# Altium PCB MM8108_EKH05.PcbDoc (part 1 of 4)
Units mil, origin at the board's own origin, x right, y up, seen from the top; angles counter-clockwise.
Board outline 6023.62 x 3425.2 mil, 4 copper layers (Top Layer, Ground Plane, Middle Layer, Bottom Layer), stack 76.15 mil thick; 188 components, 156 nets, 687 pads, 1369 vias.
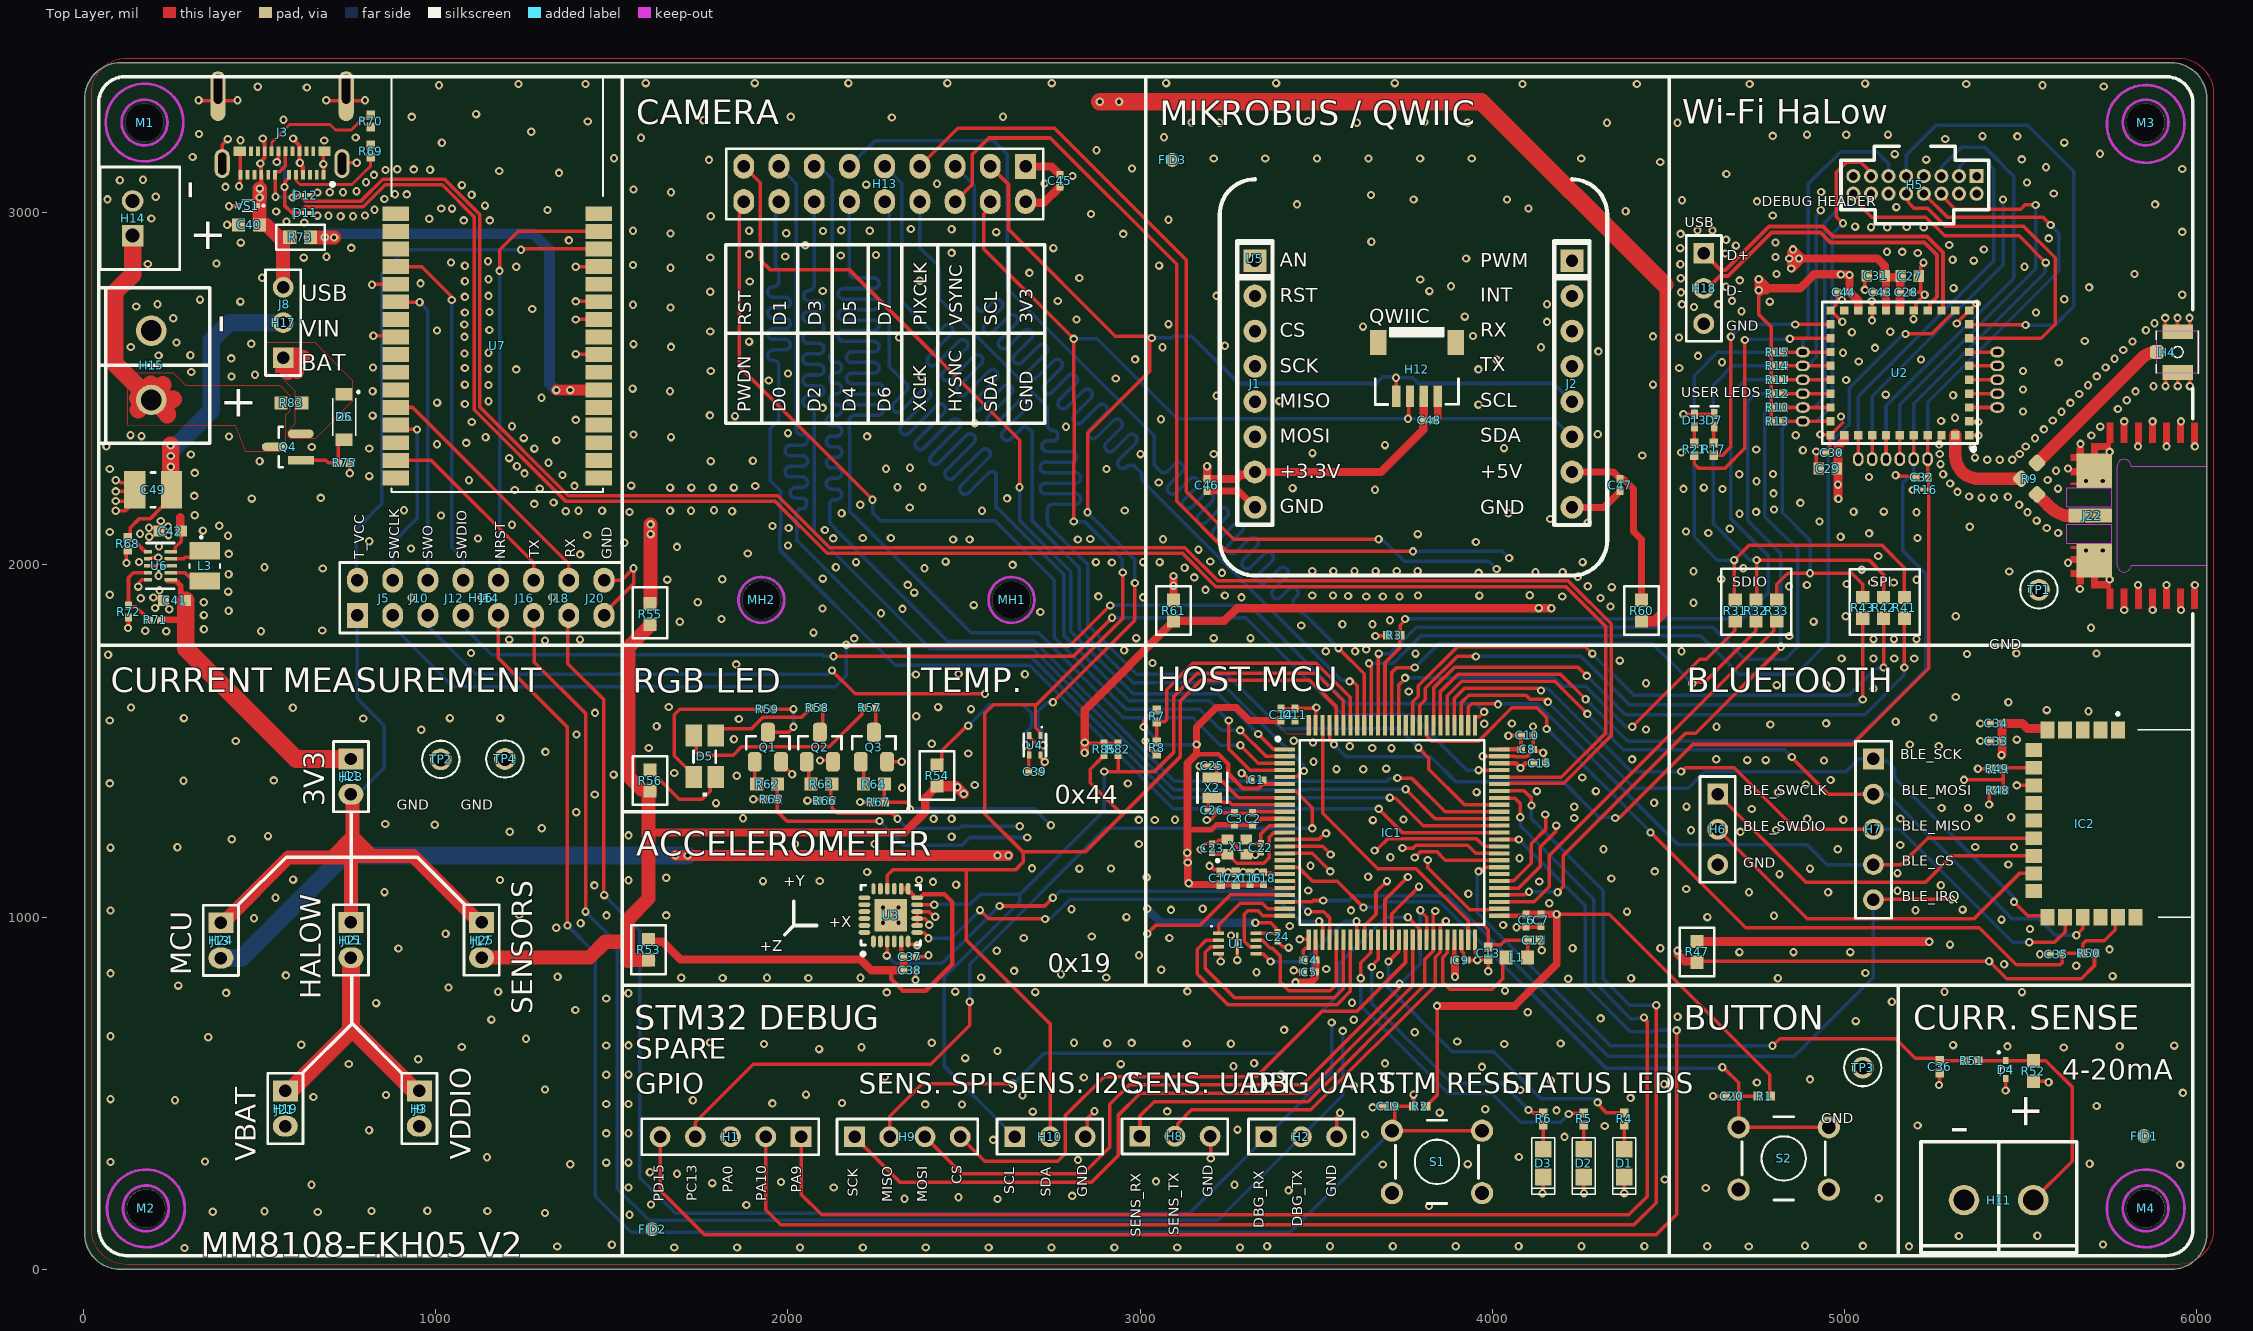
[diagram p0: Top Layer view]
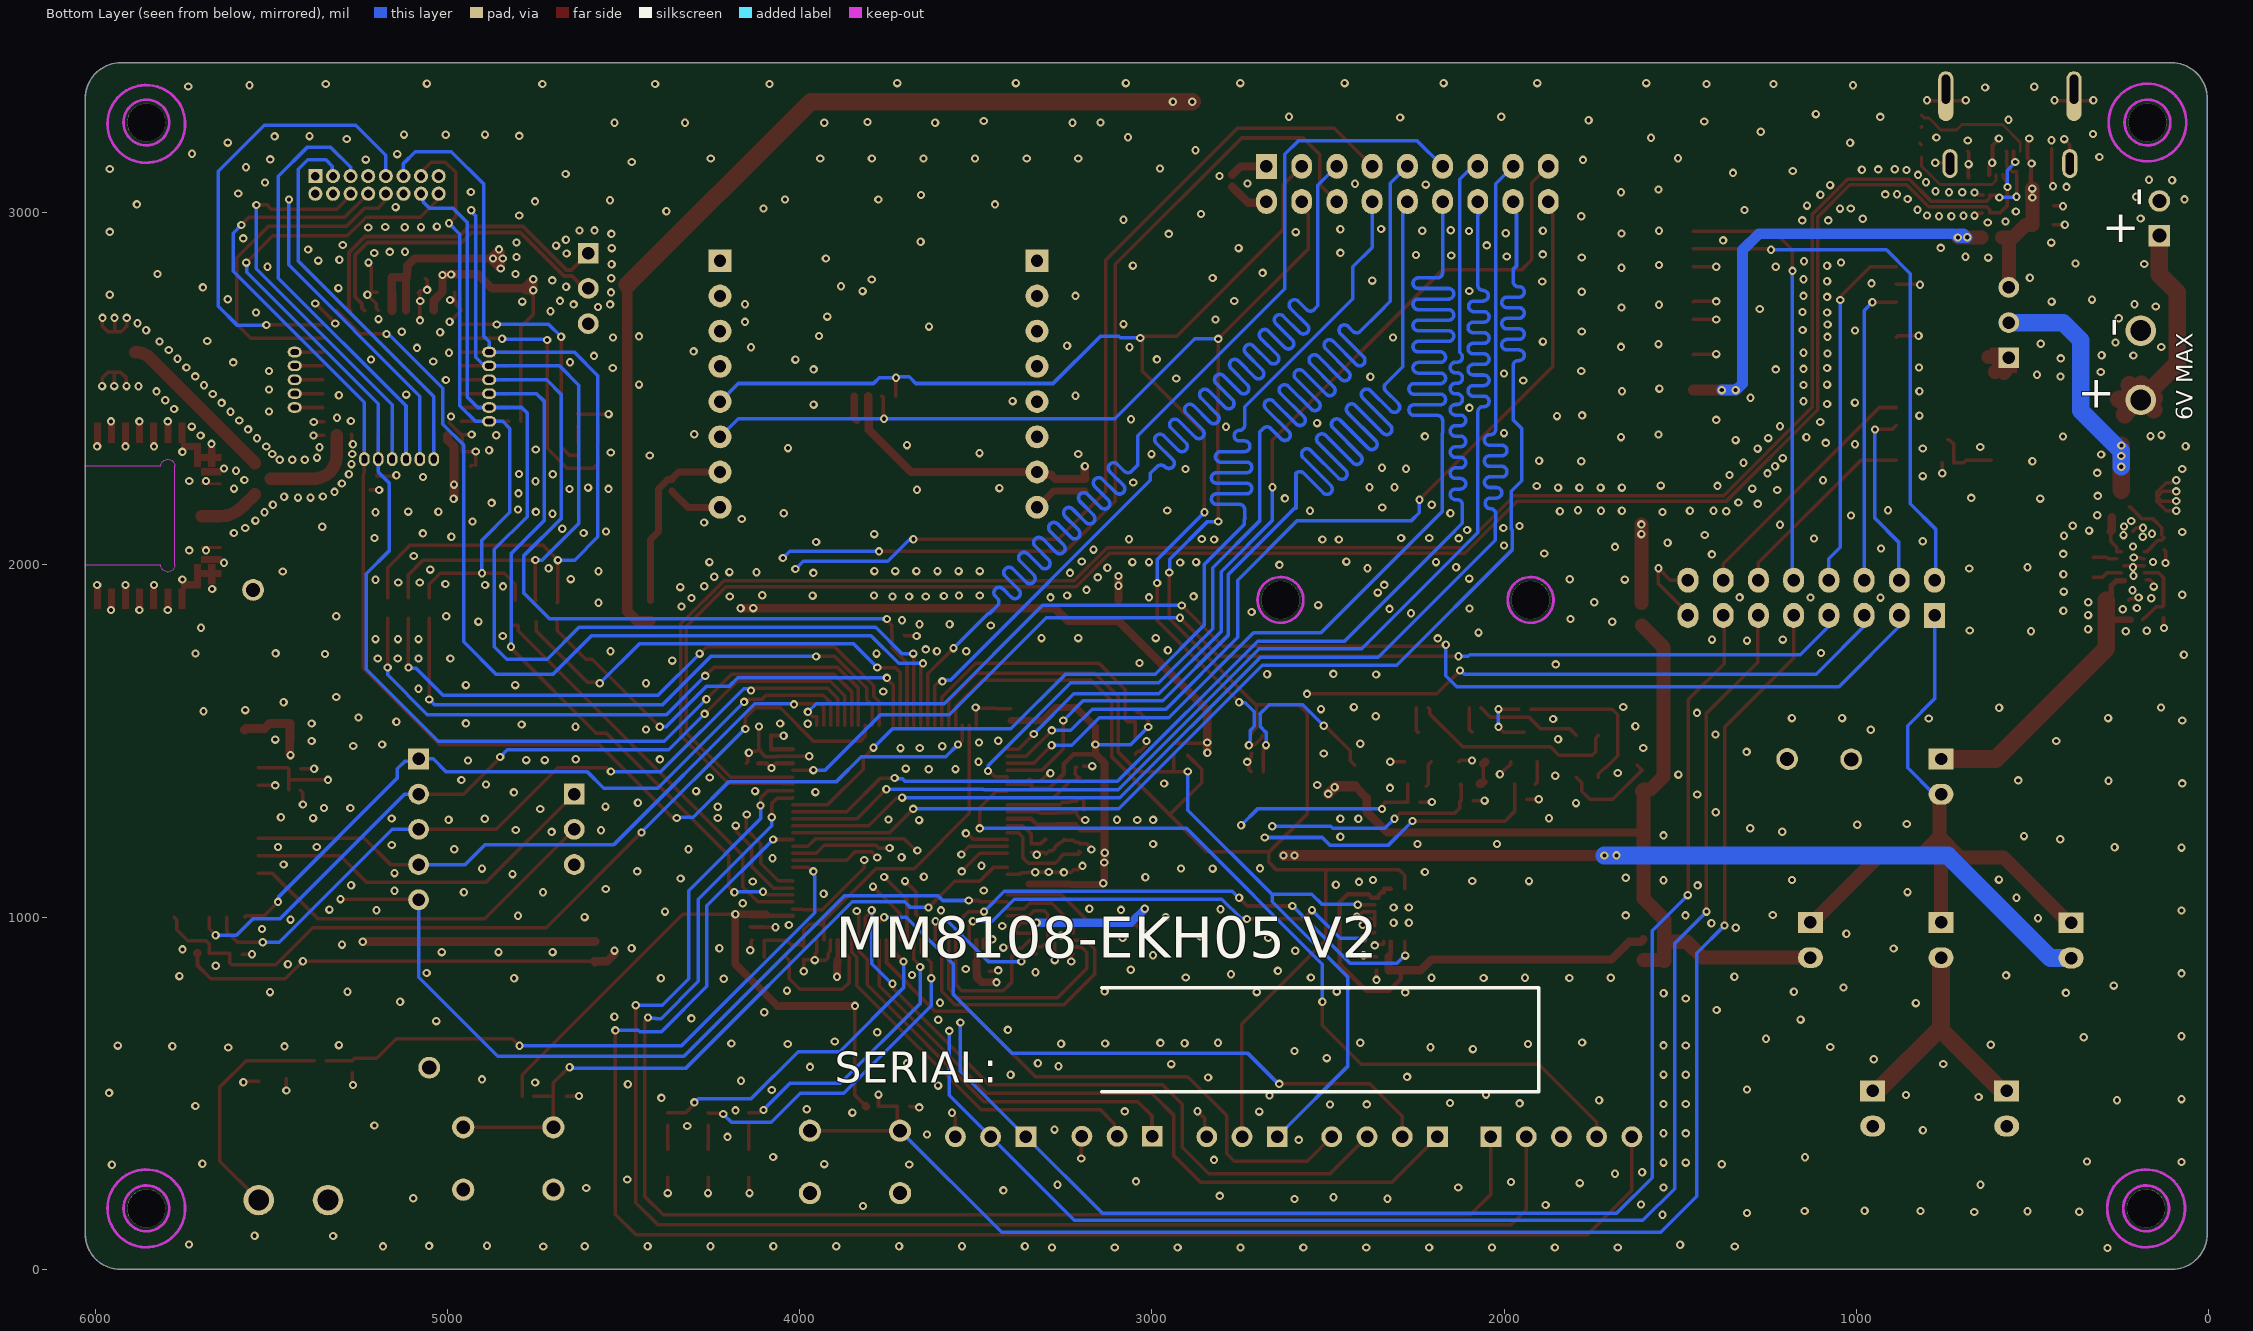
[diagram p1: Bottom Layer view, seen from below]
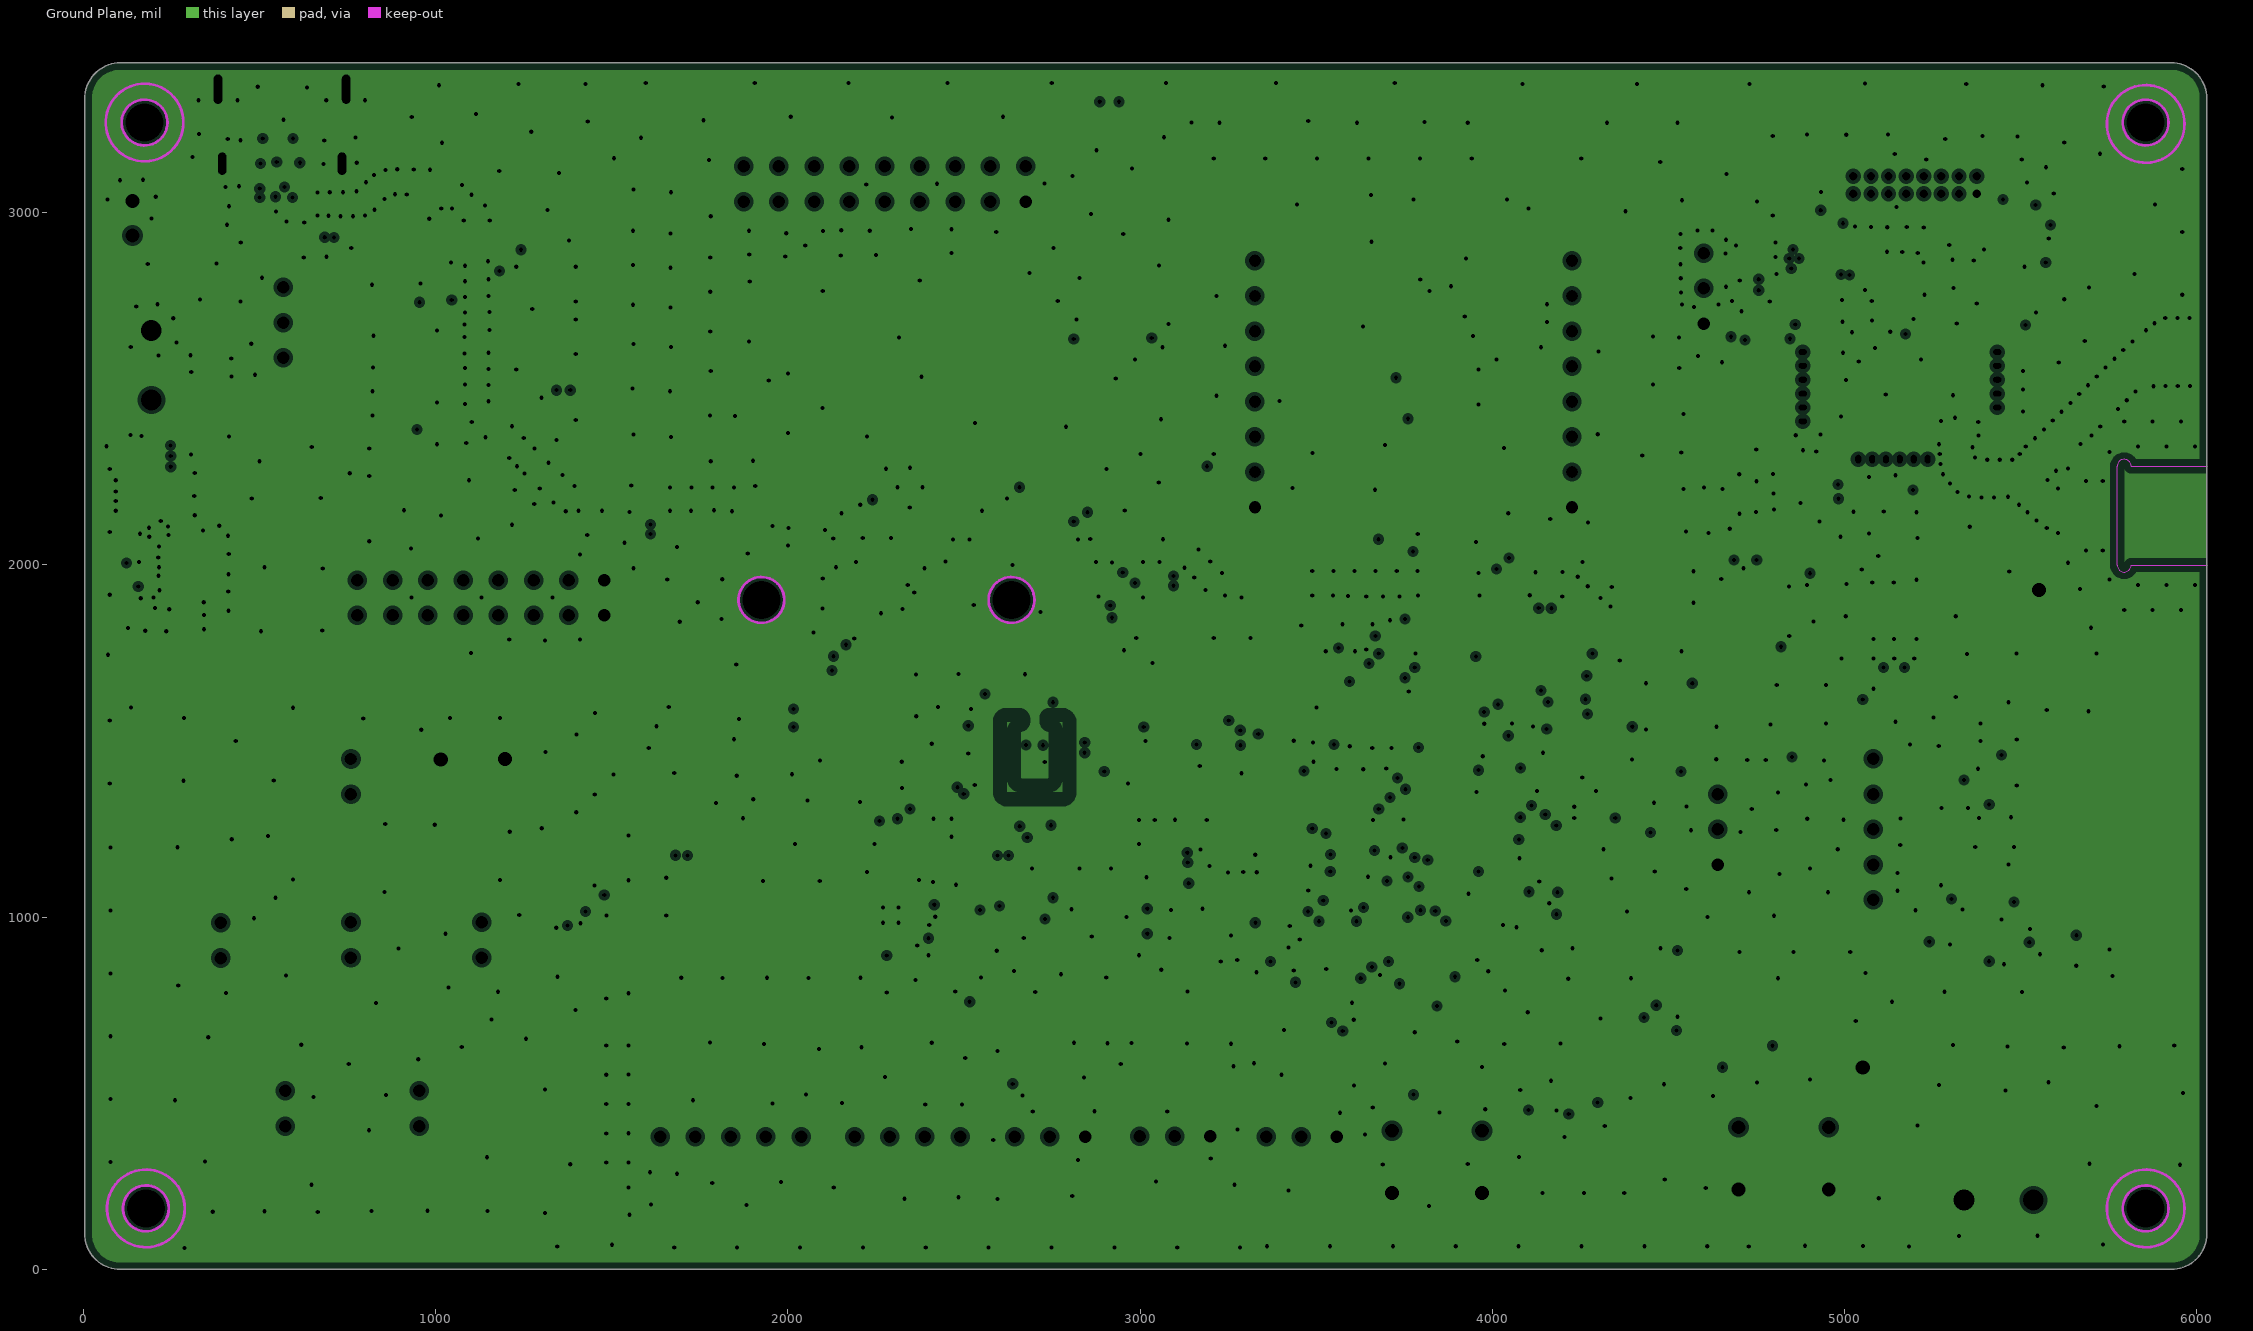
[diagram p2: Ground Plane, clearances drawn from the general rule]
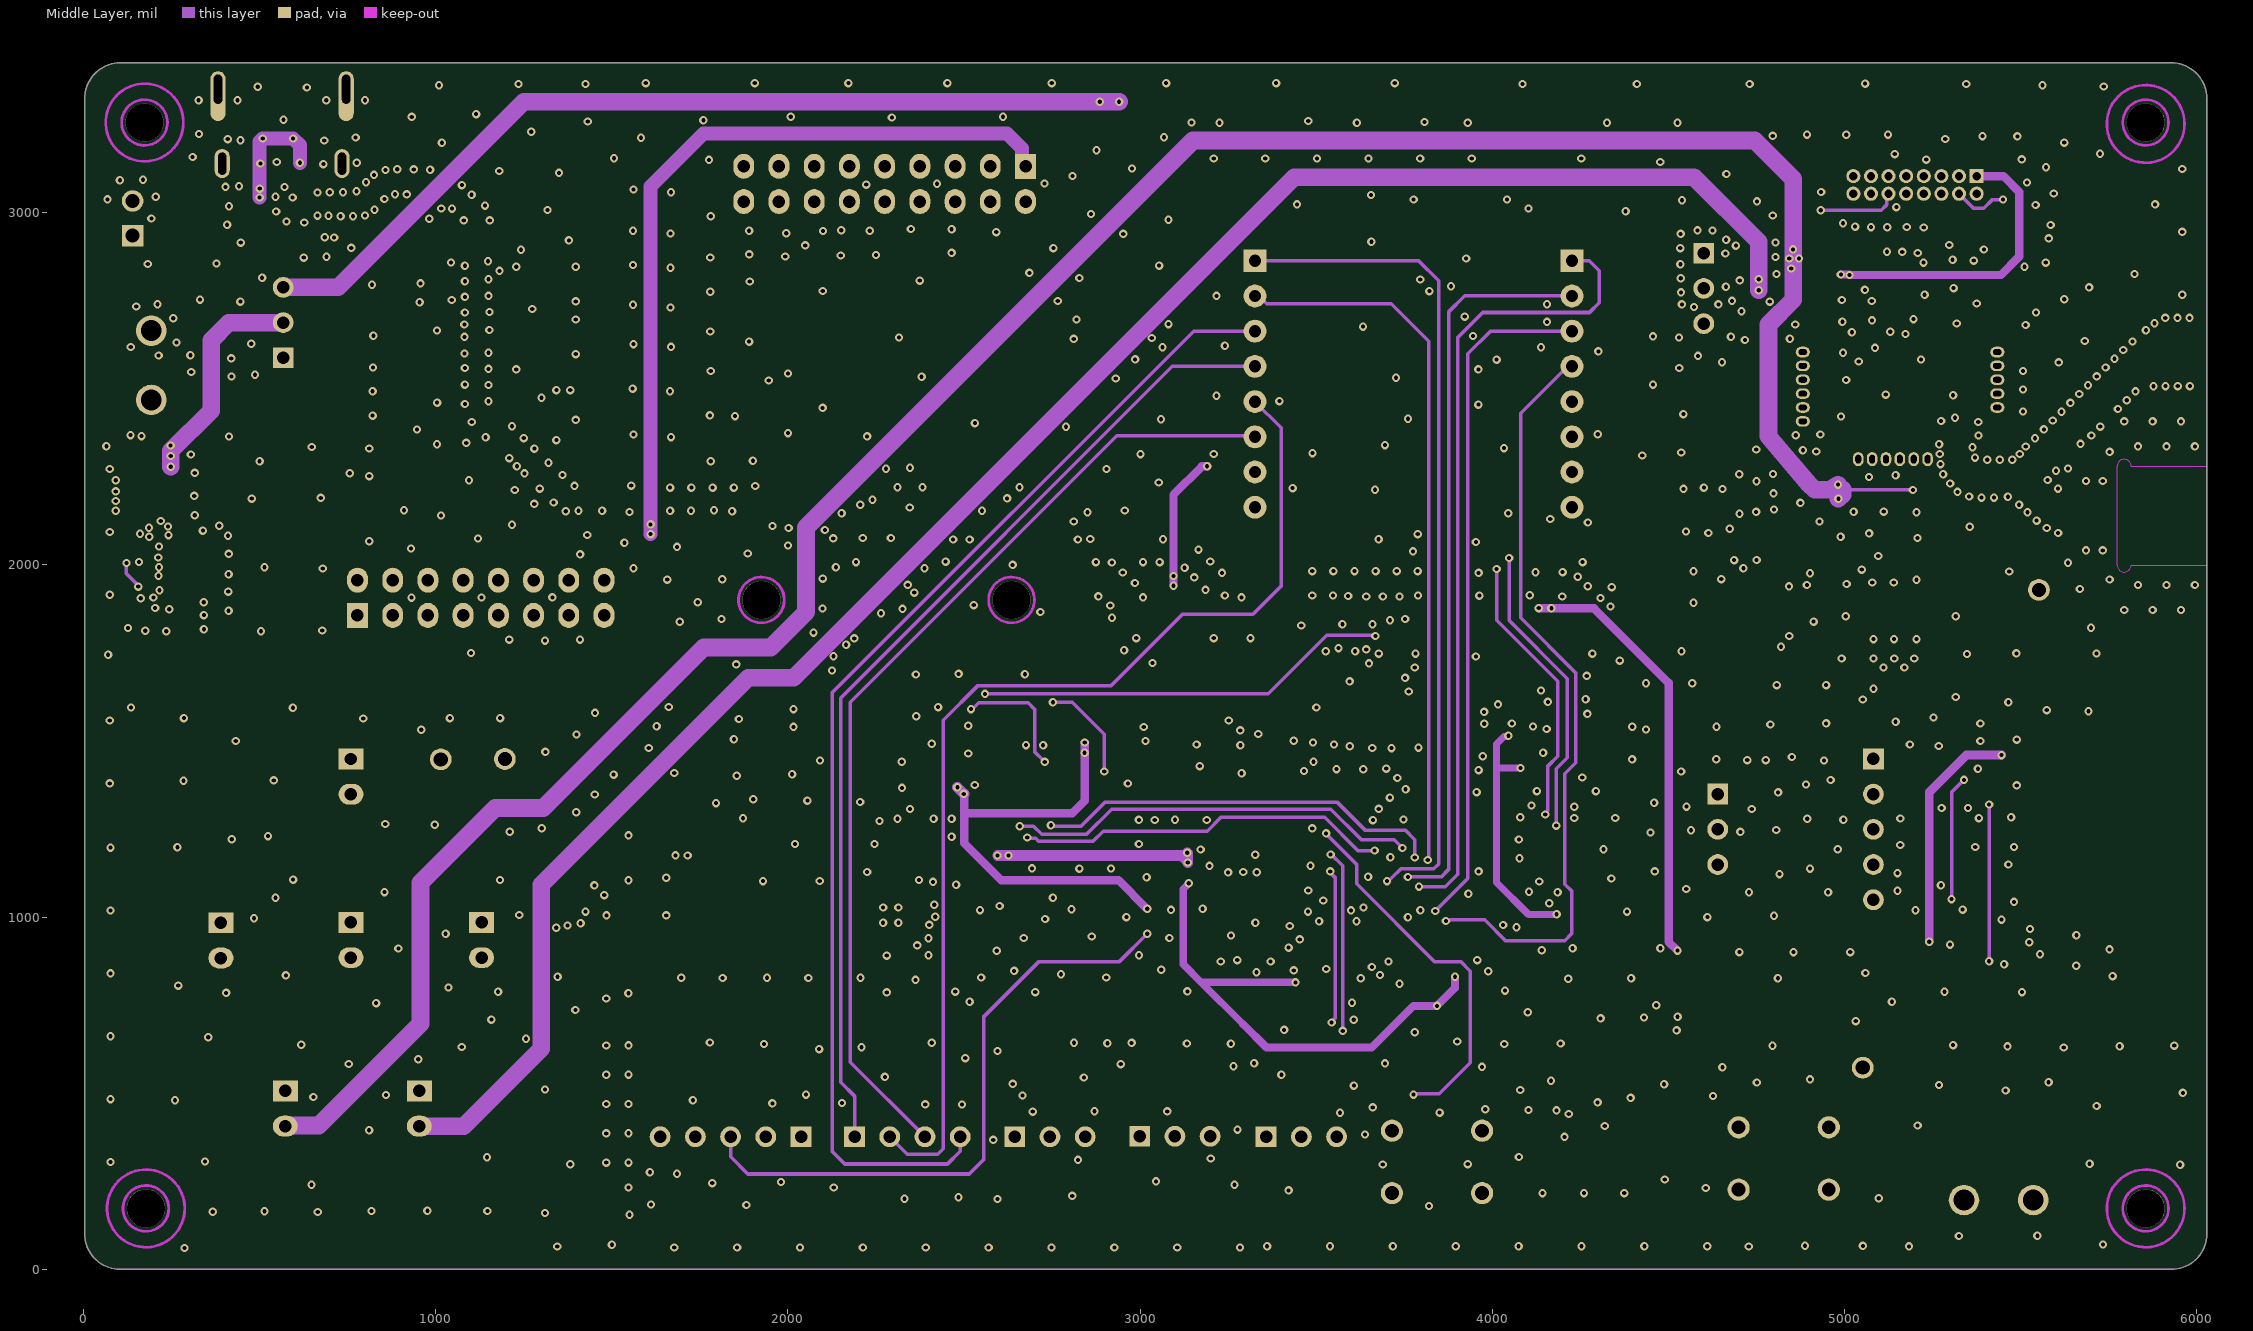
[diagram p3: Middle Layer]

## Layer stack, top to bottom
Top Solder: solder mask 0.8, SM-001, Dk 3.8
Top Layer: signal copper 1.4
Dielectric 2: prepreg 13.2, PP-006, Dk 4.11
Ground Plane: plane copper 1.25, net GND
Dielectric 1: prepreg 44.5, Core, Dk 4
Middle Layer: signal copper 1.25
Dielectric 5: prepreg 13.15, PP-006, Dk 4.11
Bottom Layer: signal copper 1.4
Bottom Solder: solder mask 0.8, SM-001, Dk 3.8

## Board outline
3.94,3188.98 3.94,3325.2 cw(c103.94,3325.2) 103.94,3425.2 5927.56,3425.2 cw(c5927.56,3325.2) 6027.56,3325.2 6027.56,100 cw(c5927.56,100) 5927.56,0 103.94,0 cw(c103.94,100) 3.94,100 3.94,275.59

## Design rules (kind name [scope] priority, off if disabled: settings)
AssemblyTestPointUsage [All] p0: scope1count=1 scope1_0_kind=Board scope1_0_value=Board scope2count=1 scope2_0_kind=Board scope2_0_value=Board commentlength=0
AssemblyTestPointUsage [All] p1: allowmultiple=TRUE
AssemblyTestpoint [All] p0: scope1count=1 scope1_0_kind=Board scope1_0_value=Board scope2count=1 scope2_0_kind=Board scope2_0_value=Board commentlength=0
AssemblyTestpoint [All] p1: testpointundercomponent=TRUE minsize=40 maxsize=100 preferedsize=60 minholesize=0 maxholesize=40 preferedholesize=32 testpointgrid=1 usegrid=FALSE gridtolerance=0.01 allowsidetop=TRUE
BoardOutlineClearance [All] p0 off: scope1count=1 scope1_0_kind=Board scope1_0_value=Board scope2count=1 scope2_0_kind=Board scope2_0_value=Board commentlength=140 gap=12 // Protel DXP Scope 1 Expression Was: (not OnTopSilkscreen) AND (NOT OnBottomSilkscreen) and (not OnMultiLayer) and (not InComponent('H3'))
BoardOutlineClearance [(not OnTopSilkscreen) AND (NOT OnBottomSilkscreen) and (not OnMultiLayer) and (not InComponent('H3'))] p1: gap=12 ignorepadtopadclearanceinfootprint=FALSE
Clearance Clearance_RF [All] p0: scope1count=1 scope1_0_kind=NetClass scope1_0_value="50 OHMs" scope2count=1 scope2_0_kind=Board scope2_0_value=Board commentlength=0 gap=78.74
Clearance Clearance_SMA [All] p0: scope1count=1 scope1_0_kind=Component scope1_0_value=J22 scope2count=1 scope2_0_kind=Component scope2_0_value=J22 commentlength=0 gap=0.01
Clearance Clearance_1 [All] p0: scope1count=1 scope1_0_kind=Board scope1_0_value=Board scope2count=1 scope2_0_kind=Board scope2_0_value=Board commentlength=0 gap=6
Clearance Clearance_USB [All] p0 off: scope1count=1 scope1_0_kind=Board scope1_0_value=Board scope2count=1 scope2_0_kind=Board scope2_0_value=Board commentlength=65 gap=6 // Protel DXP Scope 1 Expression Was: InDifferentialPair('USBC')
Clearance Clearance_RF_Poly [All] p0 off: scope1count=1 scope1_0_kind=Board scope1_0_value=Board scope2count=1 scope2_0_kind=NetClass scope2_0_value="50 OHMs" commentlength=50 gap=6.61 // Protel DXP Scope 1 Expression Was: (InPolygon)
Clearance Clearance_RF_Poly [(InPolygon) vs InNetClass('50 OHMs')] p1: gap=6.61 ignorepadtopadclearanceinfootprint=TRUE
Clearance Clearance_SMA [InComponent('J22') vs InComponent('J22')] p2: gap=0.01 ignorepadtopadclearanceinfootprint=TRUE
Clearance Clearance_USB [InDifferentialPair('USBC')] p3: gap=6 ignorepadtopadclearanceinfootprint=TRUE
Clearance Clearance_1 [All] p4: gap=6 ignorepadtopadclearanceinfootprint=TRUE
Clearance Clearance_RF [InNetClass('50 OHMs')] p5: gap=78.74 ignorepadtopadclearanceinfootprint=TRUE except(1.97: Arc-Arc Arc-Track Arc-SMDPad Arc-THPad Track-Track Track-SMDPad Track-THPad)
ComponentClearance [All] p0: scope1count=1 scope1_0_kind=Board scope1_0_value=Board scope2count=1 scope2_0_kind=Board scope2_0_value=Board commentlength=0 gap=10 collisioncheckmode=3
DiffPairsRouting DiffPairsRouting_MM [All] p0 off: scope1count=1 scope1_0_kind=Board scope1_0_value=Board scope2count=1 scope2_0_kind=Board scope2_0_value=Board commentlength=66 // Protel DXP Scope 1 Expression Was: InDifferentialPair('USB_D')
DiffPairsRouting DiffPairsRouting_USBC [All] p0 off: scope1count=1 scope1_0_kind=Board scope1_0_value=Board scope2count=1 scope2_0_kind=Board scope2_0_value=Board commentlength=65 // Protel DXP Scope 1 Expression Was: InDifferentialPair('USBC')
DiffPairsRouting DiffPairsRouting_MM [InDifferentialPair('USB_D')] p1: maxlimit=10 minlimit=6 mostfreqgap=10 toplayer_maxgap=6 toplayer_prefgap=6 toplayer_minwidth=11.13 toplayer_maxwidth=11.13 toplayer_prefwidth=11.13 impedanceprofiledriven=TRUE impedanceprofileid={FA8D62EB-FDD2-4305-96CF-BF7F0CD6B75F} impedanceprofilevalue=90.000000 maxuncoupledlength=500
DiffPairsRouting DiffPairsRouting_USBC [InDifferentialPair('USBC')] p2 off: maxlimit=10 minlimit=5 mostfreqgap=10 toplayer_mingap=6 toplayer_maxgap=6 toplayer_prefgap=6 toplayer_minwidth=11.13 toplayer_maxwidth=11.13 toplayer_prefwidth=11.13 impedanceprofiledriven=TRUE impedanceprofileid={FA8D62EB-FDD2-4305-96CF-BF7F0CD6B75F} impedanceprofilevalue=90.000000 maxuncoupledlength=500
FabricationTestPointUsage [All] p0 off: scope1count=1 scope1_0_kind=Board scope1_0_value=Board scope2count=1 scope2_0_kind=Board scope2_0_value=Board commentlength=0 valid=0 allowmultiple=FALSE
FabricationTestPointUsage [All] p1 off: valid=0 allowmultiple=FALSE
FabricationTestpoint [All] p0 off: scope1count=1 scope1_0_kind=Board scope1_0_value=Board scope2count=1 scope2_0_kind=Board scope2_0_value=Board commentlength=63 side=1 testpointundercomponent=TRUE minsize=40 maxsize=100 preferedsize=60 minholesize=0 maxholesize=40 preferedholesize=32 testpointgrid=1 // Protel DXP Scope 1 Expression Was: (IsPad And OnMultiLayer)
FabricationTestpoint [(IsPad And OnMultiLayer)] p1 off: side=1 testpointundercomponent=TRUE minsize=40 maxsize=100 preferedsize=60 minholesize=0 maxholesize=40 preferedholesize=32 testpointgrid=1 allowsidetop=TRUE usegrid=TRUE gridtolerance=0.01
FanoutControl Fanout_Default [All] p0 off: scope1count=1 scope1_0_kind=Board scope1_0_value=Board scope2count=1 scope2_0_kind=Board scope2_0_value=Board commentlength=30 // Fanout_Default (Default Rule)
FanoutControl Fanout_Small [All] p0 off: scope1count=1 scope1_0_kind=Board scope1_0_value=Board scope2count=1 scope2_0_kind=Board scope2_0_value=Board commentlength=84 // Protel DXP Scope 1 Expression Was: (CompPinCount < 5)   Fanout_Small (Default Rule)
FanoutControl Fanout_SOIC [All] p0 off: scope1count=1 scope1_0_kind=Board scope1_0_value=Board scope2count=1 scope2_0_kind=Board scope2_0_value=Board commentlength=71 // Protel DXP Scope 1 Expression Was: IsSOIC   Fanout_SOIC (Default Rule)
FanoutControl Fanout_LCC [All] p0 off: scope1count=1 scope1_0_kind=Board scope1_0_value=Board scope2count=1 scope2_0_kind=Board scope2_0_value=Board commentlength=69 // Protel DXP Scope 1 Expression Was: IsLCC   Fanout_LCC (Default Rule)
FanoutControl Fanout_BGA [All] p0 off: scope1count=1 scope1_0_kind=Board scope1_0_value=Board scope2count=1 scope2_0_kind=Board scope2_0_value=Board commentlength=69 // Protel DXP Scope 1 Expression Was: IsBGA   Fanout_BGA (Default Rule)
FanoutControl Fanout_BGA [IsBGA] p1 off: bgadir=Out bgaviamode=Centered fanoutstyle=Auto fanoutdirection=Alternating viagrid=1 // Fanout_BGA (Default Rule)
FanoutControl Fanout_LCC [IsLCC] p2 off: bgadir=Out bgaviamode=Centered fanoutstyle=Auto fanoutdirection=Alternating viagrid=1 // Fanout_LCC (Default Rule)
FanoutControl Fanout_SOIC [IsSOIC] p3 off: bgadir=Out bgaviamode=Centered fanoutstyle=Auto fanoutdirection=Alternating viagrid=1 // Fanout_SOIC (Default Rule)
FanoutControl Fanout_Small [(CompPinCount < 5)] p4 off: bgadir=Out bgaviamode=Centered fanoutstyle=Auto fanoutdirection=OutThenIn viagrid=1 // Fanout_Small (Default Rule)
FanoutControl Fanout_Default [All] p5 off: bgadir=Out bgaviamode=Centered fanoutstyle=Auto fanoutdirection=Alternating viagrid=1 // Fanout_Default (Default Rule)
Height [All] p0 off: scope1count=1 scope1_0_kind=Board scope1_0_value=Board scope2count=1 scope2_0_kind=Board scope2_0_value=Board commentlength=0
Height "Under Socket" [All] p0 off: scope1count=1 scope1_0_kind=Board scope1_0_value=Board scope2count=1 scope2_0_kind=Board scope2_0_value=Board commentlength=64 // Protel DXP Scope 1 Expression Was: WithinRoom('ROOM_SOCKET')
Height "POGO Pins" [All] p0: scope1count=1 scope1_0_kind=ComponentClass scope1_0_value=POGO scope2count=1 scope2_0_kind=Board scope2_0_value=Board commentlength=0
Height TP1 [All] p0: scope1count=1 scope1_0_kind=Component scope1_0_value=TP1 scope2count=1 scope2_0_kind=Board scope2_0_value=Board commentlength=0
Height TP1 [InComponent('TP1')] p1: minheight=0 maxheight=472.44 prefheight=118.11
Height "POGO Pins" [InComponentClass('POGO')] p2: minheight=0 maxheight=275.59 prefheight=196.85
Height "Under Socket" [WithinRoom('ROOM_SOCKET')] p3: minheight=0 maxheight=157.48 prefheight=118.11
Height [All] p4 off: minheight=0 maxheight=1000 prefheight=500
HoleSize [All] p0: scope1count=1 scope1_0_kind=Board scope1_0_value=Board scope2count=1 scope2_0_kind=Board scope2_0_value=Board commentlength=0 absolutevalues=TRUE maxlimit=200 minlimit=6 maxpercent=80.000 minpercent=20.000
HoleSize [All] p1: absolutevalues=TRUE maxlimit=200 minlimit=6 maxpercent=80.000 minpercent=20.000
HoleToHoleClearance [All] p0: scope1count=1 scope1_0_kind=Board scope1_0_value=Board scope2count=1 scope2_0_kind=Board scope2_0_value=Board commentlength=0
HoleToHoleClearance [All] p1: gap=8 allowstackedmicrovias=TRUE
LayerPairs [All] p0 off: scope1count=1 scope1_0_kind=Board scope1_0_value=Board scope2count=1 scope2_0_kind=Board scope2_0_value=Board commentlength=0 enforce=TRUE
LayerPairs [All] p1 off: enforce=TRUE
MatchedLengths SDIO_2 [All] p0: scope1count=1 scope1_0_kind=NetClass scope1_0_value=SDIO_2 scope2count=1 scope2_0_kind=Board scope2_0_value=Board commentlength=0 tolerance=2000 amplitude=200 gap=20 style=90-Degree
MatchedLengths DCMI [All] p0: scope1count=1 scope1_0_kind=NetClass scope1_0_value=DCMI scope2count=1 scope2_0_kind=Board scope2_0_value=Board commentlength=0 tolerance=1000 amplitude=200 gap=20 style=90-Degree
MatchedLengths SDIO [All] p0: scope1count=1 scope1_0_kind=NetClass scope1_0_value=SDIO scope2count=1 scope2_0_kind=Board scope2_0_value=Board commentlength=0 tolerance=2000 amplitude=200 gap=20 style=90-Degree
MatchedLengths MatchLengths_U1_Passives_J5 [All] p0 off: scope1count=1 scope1_0_kind=Board scope1_0_value=Board scope2count=1 scope2_0_kind=Board scope2_0_value=Board commentlength=98 tolerance=50 amplitude=200 gap=20 style=90-Degree // Protel DXP Scope 1 Expression Was: InxSignalClass('xSignals_U1_Passives_J5_MatchLengthsClass')
MatchedLengths MatchLengths_U1_Passives_J5_1 [All] p0 off: scope1count=1 scope1_0_kind=Board scope1_0_value=Board scope2count=1 scope2_0_kind=Board scope2_0_value=Board commentlength=100 tolerance=50 amplitude=200 gap=20 style=90-Degree // Protel DXP Scope 1 Expression Was: InxSignalClass('xSignals_U1_Passives_J5_MatchLengthsClass_1')
MatchedLengths DCMI [InNetClass('DCMI')] p1: tolerance=1000 checknetsindiffpair=FALSE checkdiffpairvsdiffpair=TRUE checkxsignals=TRUE checkothers=TRUE
MatchedLengths SDIO [InNetClass('SDIO')] p2: tolerance=2000 checknetsindiffpair=FALSE checkdiffpairvsdiffpair=TRUE checkxsignals=TRUE checkothers=TRUE
MatchedLengths SDIO_2 [InNetClass('SDIO_2')] p3: tolerance=2000 checknetsindiffpair=FALSE checkdiffpairvsdiffpair=TRUE checkxsignals=TRUE checkothers=TRUE
MatchedLengths MatchLengths_U1_Passives_J5_1 [InxSignalClass('xSignals_U1_Passives_J5_MatchLengthsClass_1')] p4: tolerance=50 checknetsindiffpair=FALSE checkdiffpairvsdiffpair=TRUE checkxsignals=TRUE checkothers=TRUE
MatchedLengths MatchLengths_U1_Passives_J5 [InxSignalClass('xSignals_U1_Passives_J5_MatchLengthsClass')] p5: tolerance=50 checknetsindiffpair=FALSE checkdiffpairvsdiffpair=TRUE checkxsignals=TRUE checkothers=TRUE
MinimumSolderMaskSliver [All] p0 off: scope1count=1 scope1_0_kind=Board scope1_0_value=Board scope2count=1 scope2_0_kind=Board scope2_0_value=Board commentlength=96 // Protel DXP Scope 1 Expression Was: not InComponent('U4','U1','U5','U6','U7','U8','U9','U10')
MinimumSolderMaskSliver [not InComponent('U4','U1','U5','U6','U7','U8','U9','U10')] p1: minsoldermaskwidth=1
NetAntennae [All] p0: scope1count=1 scope1_0_kind=Board scope1_0_value=Board scope2count=1 scope2_0_kind=Board scope2_0_value=Board commentlength=0
PasteMaskExpansion [All] p0: scope1count=1 scope1_0_kind=Board scope1_0_value=Board scope2count=1 scope2_0_kind=Board scope2_0_value=Board commentlength=0 expansion=0
PlaneClearance PlaneClearance_Etna_Test_Pads [All] p0 off: scope1count=1 scope1_0_kind=Board scope1_0_value=Board scope2count=1 scope2_0_kind=Board scope2_0_value=Board commentlength=70 clearance=8 // Protel DXP Scope 1 Expression Was: IsPad AND (SlotHoleLength = 24)
PlaneClearance [All] p0: scope1count=1 scope1_0_kind=Board scope1_0_value=Board scope2count=1 scope2_0_kind=Board scope2_0_value=Board commentlength=0 clearance=10
PlaneClearance PlaneClearance_Etna_Test_Pads [IsPad AND (SlotHoleLength = 24)] p1: clearance=8
PlaneClearance [All] p2: clearance=10
PlaneConnect [All] p0: scope1count=1 scope1_0_kind=Board scope1_0_value=Board scope2count=1 scope2_0_kind=Board scope2_0_value=Board commentlength=0 planeconnectstyle=Relief reliefexpansion=20 reliefentries=4 reliefconductorwidth=10 reliefairgap=10
PlaneConnect PlaneConnect_1 [All] p0 off: scope1count=1 scope1_0_kind=Board scope1_0_value=Board scope2count=1 scope2_0_kind=Board scope2_0_value=Board commentlength=166 planeconnectstyle=Relief reliefexpansion=15.75 reliefentries=4 reliefconductorwidth=10 reliefairgap=7.87 // Protel DXP Scope 1 Expression Was: (InComponent('J5') OR InComponent('J6') OR InComponent('J13') OR InComponent('J11') OR InComponent('J12')) OR InComponent('H3')
PlaneConnect PlaneConnect_1 [(InComponent('J5') OR InComponent('J6') OR InComponent('J13') OR InComponent('J11') OR InComponent('J12')) OR InComponent('H3')] p1: planeconnectstyle=Relief reliefexpansion=15.75 reliefentries=4 reliefconductorwidth=10 reliefairgap=7.87
PlaneConnect [All] p2: pad.planeconnectstyle=Relief pad.reliefexpansion=20 pad.reliefentries=4 pad.reliefconductorwidth=10 pad.reliefairgap=10 via.planeconnectstyle=Direct via.reliefexpansion=20 via.reliefentries=4 via.reliefconductorwidth=10 via.reliefairgap=10
PolygonConnect [All] p0: scope1count=1 scope1_0_kind=Board scope1_0_value=Board scope2count=1 scope2_0_kind=Board scope2_0_value=Board commentlength=0 connectstyle=Relief reliefconductorwidth=10 reliefentries=4 polygonreliefangle="90 Angle"
PolygonConnect PolygonConnect_1 [All] p0 off: scope1count=1 scope1_0_kind=Net scope1_0_value=GND scope2count=1 scope2_0_kind=Board scope2_0_value=Board commentlength=145 connectstyle=Relief reliefconductorwidth=10 reliefentries=4 polygonreliefangle="90 Angle" // Protel DXP Scope 2 Expression Was: (InComponent('J5') OR InComponent('J6') OR InComponent('J13') OR InComponent('J11') OR InComponent('J12'))
PolygonConnect PolygonConnect_1 [InNet('GND') vs (InComponent('J5') OR InComponent('J6') OR InComponent('J13') OR InComponent('J11') OR InComponent('J12'))] p1: connectstyle=Relief reliefconductorwidth=10 reliefentries=4 polygonreliefangle="90 Angle" airgapwidth=7.87
PolygonConnect [All] p2: thpad.connectstyle=Relief thpad.reliefconductorwidth=10 thpad.reliefentries=4 thpad.polygonreliefangle="90 Angle" thpad.airgapwidth=10 smdpad.connectstyle=Direct smdpad.reliefconductorwidth=10 smdpad.reliefentries=4 smdpad.polygonreliefangle="90 Angle" smdpad.airgapwidth=10 via.connectstyle=Direct via.reliefconductorwidth=10 via.reliefentries=4 via.polygonreliefangle="90 Angle" via.airgapwidth=10
RoutingCorners [All] p0: scope1count=1 scope1_0_kind=Board scope1_0_value=Board scope2count=1 scope2_0_kind=Board scope2_0_value=Board commentlength=0 cornerstyle=45-Degree minsetback=100 maxsetback=100
RoutingLayers [All] p0: scope1count=1 scope1_0_kind=Board scope1_0_value=Board scope2count=1 scope2_0_kind=Board scope2_0_value=Board commentlength=0 top layer=Automatic mid layer 1=Automatic bottom layer=Automatic
RoutingPriority [All] p0: scope1count=1 scope1_0_kind=Board scope1_0_value=Board scope2count=1 scope2_0_kind=Board scope2_0_value=Board commentlength=0
RoutingTopology [All] p0: scope1count=1 scope1_0_kind=Board scope1_0_value=Board scope2count=1 scope2_0_kind=Board scope2_0_value=Board commentlength=0 topology=Shortest
RoutingVias [All] p0: scope1count=1 scope1_0_kind=Board scope1_0_value=Board scope2count=1 scope2_0_kind=Board scope2_0_value=Board commentlength=0 holewidth=11.81 width=23.62 viastyle="Through Hole" minholewidth=8 minwidth=19.68 maxholewidth=28 maxwidth=50
RoutingVias [All] p1: holewidth=11.81 width=23.62 viastyle="Through Hole" minholewidth=8 minwidth=19.68 maxholewidth=28 maxwidth=50
ShortCircuit [All] p0: scope1count=1 scope1_0_kind=Board scope1_0_value=Board scope2count=1 scope2_0_kind=Board scope2_0_value=Board commentlength=0 allowed=FALSE
SilkToBoardRegionClearance [All] p0: scope1count=1 scope1_0_kind=Board scope1_0_value=Board scope2count=1 scope2_0_kind=Board scope2_0_value=Board commentlength=0
SilkToSilkClearance [All] p0: scope1count=1 scope1_0_kind=Board scope1_0_value=Board scope2count=1 scope2_0_kind=Board scope2_0_value=Board commentlength=0
SilkToSilkClearance [All] p1: silktosilkclearance=8
SilkToSolderMaskClearance [All] p0 off: scope1count=1 scope1_0_kind=Board scope1_0_value=Board scope2count=1 scope2_0_kind=Board scope2_0_value=Board commentlength=44 // Protel DXP Scope 1 Expression Was: IsPad
SilkToSolderMaskClearance [IsPad] p1: minsilkscreentomaskgap=4 clearancetoexposedcopper=TRUE
SolderMaskExpansion [All] p0: scope1count=1 scope1_0_kind=Board scope1_0_value=Board scope2count=1 scope2_0_kind=Board scope2_0_value=Board commentlength=0 expansion=4
SolderMaskExpansion [All] p1: expansion=4 istentingtop=FALSE
SupplyNets [All] p0: scope1count=1 scope1_0_kind=Net scope1_0_value=GND scope2count=1 scope2_0_kind=Board scope2_0_value=Board commentlength=0 voltage=0.000
SupplyNets SupplyNets_7 [All] p0: scope1count=1 scope1_0_kind=Net scope1_0_value=VDD_PA scope2count=1 scope2_0_kind=Board scope2_0_value=Board commentlength=0 voltage=4.000
SupplyNets SupplyNets_6 [All] p0: scope1count=1 scope1_0_kind=Net scope1_0_value=VDD_LNA scope2count=1 scope2_0_kind=Board scope2_0_value=Board commentlength=0 voltage=4.000
SupplyNets SupplyNets_5 [All] p0: scope1count=1 scope1_0_kind=Net scope1_0_value=VDD_FEM scope2count=1 scope2_0_kind=Board scope2_0_value=Board commentlength=0 voltage=4.000
SupplyNets SupplyNets_4 [All] p0: scope1count=1 scope1_0_kind=Net scope1_0_value=VDD5_RPi scope2count=1 scope2_0_kind=Board scope2_0_value=Board commentlength=0 voltage=5.000
SupplyNets SupplyNets_3 [All] p0: scope1count=1 scope1_0_kind=Net scope1_0_value=VDD5 scope2count=1 scope2_0_kind=Board scope2_0_value=Board commentlength=0 voltage=5.000
SupplyNets SupplyNets_2 [All] p0: scope1count=1 scope1_0_kind=Net scope1_0_value=VBAT scope2count=1 scope2_0_kind=Board scope2_0_value=Board commentlength=0 voltage=3.300
SupplyNets SupplyNets_1 [All] p0: scope1count=1 scope1_0_kind=Net scope1_0_value=VDD33 scope2count=1 scope2_0_kind=Board scope2_0_value=Board commentlength=0 voltage=3.300
SupplyNets SupplyNets_1 [InNet('VDD33')] p1: voltage=3.300
SupplyNets SupplyNets_2 [InNet('VBAT')] p2: voltage=3.300
SupplyNets SupplyNets_3 [InNet('VDD5')] p3: voltage=5.000
SupplyNets SupplyNets_4 [InNet('VDD5_RPi')] p4: voltage=5.000
SupplyNets SupplyNets_5 [InNet('VDD_FEM')] p5: voltage=4.000
SupplyNets SupplyNets_6 [InNet('VDD_LNA')] p6: voltage=4.000
SupplyNets SupplyNets_7 [InNet('VDD_PA')] p7: voltage=4.000
SupplyNets [InNet('GND')] p8: voltage=0.000
UnConnectedPin [All] p0 off: scope1count=1 scope1_0_kind=Board scope1_0_value=Board scope2count=1 scope2_0_kind=Board scope2_0_value=Board commentlength=0
UnConnectedPin [All] p1 off:
UnRoutedNet [All] p0: scope1count=1 scope1_0_kind=Board scope1_0_value=Board scope2count=1 scope2_0_kind=Board scope2_0_value=Board commentlength=0
UnRoutedNet [All] p1: checkbadconnections=TRUE
UnpouredPolygon [All] p0: scope1count=1 scope1_0_kind=Board scope1_0_value=Board scope2count=1 scope2_0_kind=Board scope2_0_value=Board commentlength=0
Width "RF Width_1" [All] p0 off: scope1count=1 scope1_0_kind=Board scope1_0_value=Board scope2count=1 scope2_0_kind=Board scope2_0_value=Board commentlength=65 maxlimit=23.62 minlimit=4.18 preferedwidth=10 // Protel DXP Scope 1 Expression Was: InDifferentialPair('USBC')
Width [All] p0: scope1count=1 scope1_0_kind=Board scope1_0_value=Board scope2count=1 scope2_0_kind=Board scope2_0_value=Board commentlength=0 maxlimit=50 minlimit=8 preferedwidth=8
Width "RF Width" [All] p0: scope1count=1 scope1_0_kind=NetClass scope1_0_value="50 OHMs" scope2count=1 scope2_0_kind=Board scope2_0_value=Board commentlength=0 maxlimit=39.37 minlimit=4.18 preferedwidth=10
Width "RF Width" [InNetClass('50 OHMs')] p1: maxlimit=39.37 minlimit=4.18 preferedwidth=10 toplayer_minwidth=35.43 toplayer_maxwidth=35.43 toplayer_prefwidth=35.43 impedanceprofiledriven=TRUE impedanceprofileid={FF55CEB2-EE64-462C-BC0D-290E837BE369} impedanceprofilevalue=50.000000 minimp=50.000000 maximp=50.000000 favimp=50.000000
Width "RF Width_1" [InDifferentialPair('USBC')] p2: maxlimit=23.62 minlimit=4.18 preferedwidth=10 toplayer_minwidth=7 minimp=50.000000 maximp=50.000000 favimp=50.000000
Width [All] p3: maxlimit=50 minlimit=8 preferedwidth=8
10 further rules are at their usual default settings.

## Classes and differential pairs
component class U_Mechanical: FID1 FID2 FID3 J5 J8 J9 J10 J11 J12 J13 J14 J15 J16 J17 J18 J20 J21 M1 M2 M3 M4 TP1 TP2 TP3 TP4
net class SDIO_2: SDMMC2_CLK SDMMC2_CMD SDMMC2_D0
net class DCMI: CAM_XCLK DCMI_D0 DCMI_D1 DCMI_D2 DCMI_D3 DCMI_D4 DCMI_D5 DCMI_D6 DCMI_D7 DCMI_HSYNC DCMI_PIXCLK DCMI_VSYNC
net class SDIO: MM_SDIO_CLK MM_SDIO_CMD MM_SDIO_D0 MM_SDIO_D1 MM_SDIO_D2 MM_SDIO_D3
net class "50 OHMs": ANT NetH4_1 NetJ22_1
component class U_Sensors: C36 C37 C38 C39 C45 C46 C47 C48 D4 D5 H8 H9 H10 H11 H12 H13 J1 J2 MH1 MH2 Q1 Q2 Q3 R51 R52 R53 R54 R55 R56 R57 R58 R59 R60 R61 R62 R63 R64 R65 R66 R67 U3 U4 U5
component class U_Power: C40 C41 C42 C49 D6 D11 D12 H3 H14 H15 H16 H17 H19 H21 H23 H24 H25 J3 L3 Q4 R68 R69 R70 R71 R72 R73 R75 R83 U6 U7 VS1
component class U_BLE_Module: C33 C34 C35 H6 H7 IC2 R47 R48 R49 R50
component class U_STM_MCU: C1 C2 C3 C4 C5 C6 C7 C8 C9 C10 C11 C12 C13 C14 C15 C16 C17 C18 C19 C20 C21 C22 C23 C24 C25 C26 D1 D2 D3 H1 H2 IC1 L1 R1 R2 R3 R4 R5 R6 R7 R8 R82 R85 S1 S2 U1 X1 X2
component class U_HaLow_Module: C27 C28 C29 C30 C31 C32 C43 C44 D7 D13 H4 H5 H18 J22 R9 R10 R11 R12 R13 R14 R15 R16 R17 R21 R31 R32 R33 R41 R42 R43 U2
differential pair USB_D: +USB_D_P -USB_D_N
differential pair " ": +USBC_P -USBC_N

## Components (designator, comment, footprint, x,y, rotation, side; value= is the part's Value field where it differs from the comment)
C1 "GRM155R61A475MEAAD" 0402_cap 3330,1390 r0 top
C2 "C1005X7R1H104K050BE" 0402_cap 3318.9,1279.53 r270 top
C3 "CL05A106MP8NUB8" 0402_cap 3267.72,1279.53 r270 top
C4 "C1005X7R1H104K050BE" 0402_cap 3480.31,877.95 r0 top
C5 "CL05A106MP8NUB8" 0402_cap 3479.02,844.11 r0 top
C6 "C1005X7R1H104K050BE" 0402_cap 4095.37,990.6 r90 top
C7 "CL05A106MP8NUB8" 0402_cap 4137.08,991.19 r90 top
C8 "C1005X7R1H104K050BE" 0402_cap 4098.43,1476.38 r180 top
C9 "CL05A106MP8NUB8" 0402_cap 3909.45,877.95 r0 top
C10 "CL05A106MP8NUB8" 0402_cap 4098.43,1515.75 r180 top
C11 "C1005X7R1H104K050BE" 0402_cap 3440,1575 r270 top
C12 "GRM155R61E225ME15D" CAPC1005X06N 4117.13,935.04 r0 top
C13 "GRM155R61E225ME15D" CAPC1005X06N 3988.19,897.64 r270 top
C14 "CL05A106MP8NUB8" 0402_cap 3400,1575 r270 top
C15 "C1005X7R1H104K050BE" 0402_cap 4133.86,1437.01 r180 top
C16 "C1005X7R1H104K050BE" 0402_cap 3311.02,1110.24 r270 top
C17 "CL05A105KA5NQNC" CAPC1005X06N 3228.35,1110.24 r270 top
C18 "C1005X7R1H104K050BE" 0402_cap 3350.39,1110.24 r270 top
C19 "LMK105BJ104KV-F" CAPC1005X06N 3704.72,462.6 r180 top
C20 "LMK105BJ104KV-F" CAPC1005X06N 4679.13,492.13 r180 top
C21 "CL05A105KA5NQNC" CAPC1005X06N 3271.65,1110.24 r270 top
C22 "GRM0335C1E120JA01D" CAPC0603X03N 3342.52,1196.85 r270 top
C23 "GRM0335C1E120JA01D" CAPC0603X03N 3203.74,1195.87 r90 top
C24 "CL03A104KQ3NNNC" CAPC0603X03N 3389.76,944.88 r90 top
C25 "GRM0335C1E120JA01D" CAPC0603X03N 3204.72,1429.13 r0 top
C26 "GRM0335C1E120JA01D" CAPC0603X03N 3204.72,1303.15 r180 top
C27 "GRM188R61E106MA73J" CAPC1608X06L 5184.9,2820.02 r0 top
C28 "C0402C104K8RACTU" 0402_cap_rnd 5174.48,2773.62 r180 top
C29 "GRM188R61E106MA73J" CAPC1608X06L 4951.48,2273.55 r180 top
C30 "C0402C104K8RACTU" 0402_cap_rnd 4963.7,2318.95 r0 top
C31 "GRM188R61E106MA73J" CAPC1608X06L 5087.77,2820.79 r180 top
C32 "GRM155R61E225ME15D" CAPC1005X06N 5218.06,2249.03 r180 top
C33 "GRM155R61E225ME15D" CAPC1005X06N 5430,1500 r180 top
C34 "C1005X7R1H104K050BE" 0402_cap 5430,1550 r0 top
C35 "GRM155R71E103KA01D" 0402_cap 5600,895 r0 top
C36 "GRM155R71E103KA01D" CAPC1005X06N 5269.69,575.2 r270 top
C37 "C1005X7R1H104K050BE" 0402_cap 2345,888 r180 top
C38 "CL05A106MP8NUB8" 0402_cap 2345,849 r180 top
C39 "C1005X7R1H104K050BE" 0402_cap 2700.79,1413.39 r180 top
C40 "GRM188R61E106MA73J" CAPC1608X06N 470,2965 r180 top
C41 "GRM188R60J226MEA0D" 0603_cap 258.5,1899.41 r0 top
C42 "GRM155R60J106ME05" 0603_cap 245.91,2095.79 r0 top
C43 "C0402C104K8RACTU" 0402_cap_rnd 5100.13,2773.62 r0 top
C44 "C0402C104K8RACTU" 0402_cap_rnd 4996.75,2774.54 r180 top
C45 "C1005X7R1H104K050BE" 0402_cap 2771.65,3090.55 r90 top
C46 "C1005X7R1H104K050BE" 0402_cap 3188.98,2226.77 r90 top
C47 "C1005X7R1H104K050BE" 0402_cap 4362.2,2226.77 r90 top
C48 "C1005X7R1H104K050BE" 0402_cap 3820,2410 r180 top
C49 "CL32A107MPVNNNE" CAPC3225X20N 197.68,2212.79 r180 top
D1 "LTST-C170KRKT" LED_0805_RED 4374.02,301.57 r270 top
D2 "LTST-C170KGKT" LED_0805_GREEN 4258.86,301.57 r270 top
D3 "LTST-C170TBKT" LED_0805_BLUE 4143.7,301.57 r270 top
D4 "ESD8351XV2T1G" SOD-523-DIODE 5456.69,566.93 r270 top
D5 "150120M173000" WL-SFCW_1206 1763.78,1456.69 r90 top
D6 "MMSZ5231B7F" SOD-123FL 740,2420 r270 top
D7 "XZVGR68W-3" LED_0402_GREEN 4629.53,2410.73 r90 top
D11 "ESDALC6V1-1U2" 0201_DIODE 630,2999.22 r0 top
D12 "ESDALC6V1-1U2" 0201_DIODE 630,3050 r0 top
D13 "XZMDK68W-2" LED_0402_RED 4572.93,2410.21 r90 top
FID1 "PAD0002" FIDUCIAL_1MM 5849.65,378.7 r90 top
FID2 "PAD0002" FIDUCIAL_1MM 1614,114 r90 top
FID3 "PAD0002" FIDUCIAL_1MM 3090.55,3149.61 r90 top
H1 "2011-1X05G00SB" "HDR1X5 - Short Gold" 1887.01,376.69 r180 top
H2 "2011-1X03G00SB" HDR1X3 3457.38,376.69 r0 top
H3 "2011-1X02G00SB-1" HDR1X2 953.41,456.69 r270 top
H4 "U.FL-R-SMT" U_FL-R-SMT 5944.88,2604.33 r270 top
H5 "FTSH-108-01-F-D-K" FTSH_108_D_K 5199.41,3078.74 r180 top locked
H6 "2011-1X03G00SB" HDR1X3 4639.37,1249.29 r270 top
H7 "2011-1X05G00SB" "HDR1X5 - Short Gold" 5081.42,1299.29 r270 top
H8 "2011-1X03G00SB" HDR1X3 3098.43,377.95 r0 top
H9 "2011-1X04G00SB" "HDR1X4 - Short Gold" 2338.88,376.69 r0 top
H10 "2011-1X03G00SB" HDR1X3 2743.7,376.69 r0 top
H11 "OSTTC020162" SCREW_TERM_2WAY_5MM 5338.58,196.85 r0 top
H12 "SM04B-SRSS-TBLFSN" SM04B-SRSS-TB 3785.59,2555.28 r90 top
H13 "PPTC092LFBN-RC" "HDR2X9 Female" 2674.41,3131.5 r180 top
H14 "B2B-XH-A" B2B-XH-A 160.12,2984.09 r90 top
H15 "OSTTC020162" SCREW_TERM_2WAY_5MM 192.6,2665.04 r270 top locked
H16 "2011-2X08TSB" "HDR2X8 Short Gold" 1077.76,1906.69 r0 top
H17 "2011-1X03G00SB" HDR1X3 566.93,2687.87 r90 top
H18 "PHA1-S103-01GA" HDR1X3 4599.79,2784.94 r270 top
H19 "2011-1X02G00SB-1" HDR1X2 572.83,456.69 r270 top
H21 "2011-1X02G00SB-1" HDR1X2 759.39,935 r270 top
H23 "2011-1X02G00SB-1" HDR1X2 759.39,1399 r270 top
H24 "2011-1X02G00SB-1" HDR1X2 390.05,934 r270 top
H25 "2011-1X02G00SB-1" HDR1X2 1130.05,935 r270 top
IC1 "STM32U585VIT6Q" STM32U585VIT6 3714.57,1240.16 r0 top locked
IC2 "BLUENRG-M2SP" BLUENRGM2SP 5725.59,1265.75 r270 top
J1 "75915-308GLF" 75915-308LF 3325.59,2863.58 r0 top
J2 "75915-308GLF" 75915-308LF 4225.59,2863.58 r0 top
J3 "2012670005" USB-C_RCP 563.78,3228.94 r180 top locked
J5 "QPC02SXGN-RC" FP-QPC02SXGN-RC-MFG 852.76,1905.51 r90 top
J8 "QPC02SXGN-RC" FP-QPC02SXGN-RC-MFG 570,2740 r90 top
J9 "QPC02SXGN-RC" FP-QPC02SXGN-RC-MFG 953.41,454.72 r270 top
J10 "QPC02SXGN-RC" FP-QPC02SXGN-RC-MFG 952.76,1905.51 r90 top
J11 "QPC02SXGN-RC" FP-QPC02SXGN-RC-MFG 760.2,1401.43 r90 top
J12 "QPC02SXGN-RC" FP-QPC02SXGN-RC-MFG 1052.76,1905.51 r90 top
J13 "QPC02SXGN-RC" FP-QPC02SXGN-RC-MFG 389.09,933.35 r90 top
J14 "QPC02SXGN-RC" FP-QPC02SXGN-RC-MFG 1152.76,1905.51 r90 top
J15 "QPC02SXGN-RC" FP-QPC02SXGN-RC-MFG 760.2,934.43 r90 top
J16 "QPC02SXGN-RC" FP-QPC02SXGN-RC-MFG 1252.76,1905.51 r90 top
J17 "QPC02SXGN-RC" FP-QPC02SXGN-RC-MFG 1131.05,932 r90 top
J18 "QPC02SXGN-RC" FP-QPC02SXGN-RC-MFG 1352.76,1905.51 r90 top
J20 "QPC02SXGN-RC" FP-QPC02SXGN-RC-MFG 1452.76,1905.51 r90 top
J21 "QPC02SXGN-RC" FP-QPC02SXGN-RC-MFG 571.85,452.76 r90 top
J22 "SM2924" SM2924-Footprint-1 5984.25,2139.76 r180 top
L1 "ASMPH-0603-2R2M-T" INDC1608X10N 4068.9,885.83 r180 top
L3 "DFE252012PR47MP2" INDC2520X120N 344.33,1997.36 r270 top
M1 "MH_300_275_NPTH" MH_300_275_NPTH 173.23,3255.91 r0 top
M2 "MH_300_275_NPTH" MH_300_275_NPTH 177.17,173.23 r0 top
M3 "MH_300_275_NPTH" MH_300_275_NPTH 5854.33,3255.91 r0 top
M4 "MH_300_275_NPTH" MH_300_275_NPTH 5854.33,173.23 r0 top
MH1 "PAD0009" MH_300_275_NPTH 2634.57,1900.63 r0 top
MH2 "PAD0009" MH_300_275_NPTH 1924.57,1900.63 r0 top
Q1 "2N7002NXAKR" SOT95P240X120_GSD-3N(SOT23-3L) 1942.91,1484.25 r0 top
Q2 "2N7002NXAKR" SOT95P240X120_GSD-3N(SOT23-3L) 2090.54,1484.25 r0 top
Q3 "2N7002NXAKR" SOT95P240X120_GSD-3N(SOT23-3L) 2244.09,1484.25 r0 top
Q4 "IRLML6401TRPBF" FP-SOT23-IPC_A 580,2335 r180 top
R1 "MCR01MZPF1002" RESC1005X04N 4771.65,492.13 r180 top
R2 "MCR01MZPF1002" RESC1005X04N 3793.31,462.6 r180 top
R3 "ERJ-2RKF1001X" RESC1005X04N 3720,1800 r0 top
R4 "ERJ-2RKF1001X" RESC1005X04N 4374.02,427.16 r270 top
R5 "ERJ-2RKF1001X" RESC1005X04N 4258.86,427.16 r270 top
R6 "ERJ-2RKF1001X" RESC1005X04N 4143.7,427.16 r270 top
R7 "MCR01MZPF1002" RESC1005X04N 3047.24,1570.87 r90 top
R8 "MCR01MZPF1002" RESC1005X04N 3047.24,1480.31 r270 top
R9 "RES_AB" 0603_RES_AB_RA 5523.62,2222.44 r315 top
R10 "MCR01MZPF4702" RESC1005X04N 4808.46,2446.85 r0 top
R11 "MCR01MZPF4702" RESC1005X04N 4808.46,2525.59 r0 top
R12 "MCR01MZPF4702" RESC1005X04N 4808.46,2486.22 r0 top
R13 "MCR01MZPF4702" RESC1005X04N 4808.46,2407.48 r0 top
R14 "MCR01MZPF4702" RESC1005X04N 4808.46,2564.96 r0 top
R15 "MCR01MZPF4702" RESC1005X04N 4808.46,2604.33 r0 top
R16 "ERJ-1GNF1002C" 0201_res_rnd 5228.56,2213.97 r180 top
R17 "RC0402FR-07330RL" RESC1005X04N 4628.08,2328.56 r90 top
R21 "RC0402FR-07330RL" RESC1005X04N 4572.58,2328.05 r90 top
R31 "RC0603JR-070RL" RESC1608X06N 4688.98,1870.08 r90 top
R32 "RC0603JR-070RL" RESC1608X06N 4748.03,1870.08 r90 top
R33 "RC0603JR-070RL" RESC1608X06N 4807.09,1870.08 r90 top
R41 "RC0603JR-070RL" RESC1608X06N 5169.29,1877.95 r270 top
R42 "RC0603JR-070RL" RESC1608X06N 5110.24,1877.95 r270 top
R43 "RC0603JR-070RL" RESC1608X06N 5051.18,1877.95 r270 top
R47 "RC0603JR-070RL" RESC1608X06N 4580.71,901.57 r90 top
R48 "RT0402BRD0710KL" RESC1005X04N 5435,1360 r0 top
R49 "RT0402BRD0710KL" RESC1005X04N 5433.07,1420.68 r180 top
R50 "MCR01MZPF4702" RESC1005X04N 5692.91,897.64 r180 top
R51 "MCR01MZPF1002" RESC1005X04N 5360.63,592.52 r180 top
R52 "RNCS0603BKE100R" RESC1608X06N 5535.43,562.99 r270 top
R53 "RC0603JR-070RL" RESC1608X06N 1604.33,907.48 r90 top
R54 "RC0603JR-070RL" RESC1608X06N 2423.23,1401.57 r90 top
R55 "RC0603JR-070RL" RESC1608X06N 1608.27,1860.24 r90 top
R56 "RC0603JR-070RL" RESC1608X06N 1608.27,1387.8 r90 top
R57 "RC0402FR-07330RL" 0402_res 2232.28,1594.49 r0 top
R58 "RC0402FR-071KL" 0402_res 2082.68,1594.49 r0 top
R59 "MCR01MZPF2200" 0402_res 1940.94,1590.55 r0 top
R60 "RC0603JR-070RL" RESC1608X06N 4423.23,1870.08 r270 top
R61 "RC0603JR-070RL" RESC1608X06N 3094.49,1870.08 r90 top
R62 "RC0603JR-070RL" RESC1608X06N 1940.94,1377.95 r180 top
R63 "RC0603JR-070RL" RESC1608X06N 2094.49,1377.95 r180 top
R64 "RC0603JR-070RL" RESC1608X06N 2244.09,1377.95 r180 top
R65 "ERJ-2RKF1002X" RESC1005X04N 1952.76,1334.65 r0 top
R66 "ERJ-2RKF1002X" RESC1005X04N 2104.72,1330.71 r0 top
R67 "ERJ-2RKF1002X" RESC1005X04N 2255.91,1326.77 r0 top
R68 "RC0402FR-07100KL" RESC1005X04N 125.83,2060.35 r270 top
R69 "MCR01MZPF5101" RESC1005X04N 815,3175 r90 top
R70 "MCR01MZPF5101" RESC1005X04N 815,3260 r270 top
R71 "RES0262" 0402_res 203.31,1843.82 r180 top
R72 "RES0263" 0402_res 127.79,1867.44 r270 top
R73 "RC0603JR-070RL" RESC1608X06N 615,2930 r180 top
R75 "RC0402FR-07330RL" RESC1005X04N 740,2290 r0 top
R82 "ERJ-2RKF1002X" 0402_res 2937.01,1476.38 r270 top
R83 "RC0603JR-070RL" RESC1608X06N 590,2460 r0 top
R85 "ERJ-2RKF1002X" 0402_res 2897.64,1476.38 r270 top
S1 "1825910-6" TL1105 3970.47,393.7 r180 top
S2 "1825910-6" TL1105 4954.72,403.54 r180 top
TP1 "TP-BLK" FP-5001-MFG 5551.18,1929.13 r0 top
TP2 "TP-BLK" FP-5001-MFG 1014.31,1448 r0 top
TP3 "TP-BLK" FP-5001-MFG 5051.18,572.68 r0 top
TP4 "TP-BLK" FP-5001-MFG 1196.19,1449 r0 top
U1 "IC FLASH 16MBIT SPI/QUAD 8USON" USON8P20X30X6 3275.59,925.2 r0 top
U2 "MM8108-MF15" MF15 5353.35,2368.11 r180 top locked
U3 "IIS328DQTR" QFN50P400X400X185_HS-25N 2291.8,1005.79 r90 top
U4 "SHT40-AD1B-R3" DFN140P150X59-4N 2700.79,1488.19 r270 top
U5 "MIKROBUS HOST" MIKROBUS_Host_SD 3325.59,2869.58 r0 top locked
U6 "TPS63802DLAR" TPS63802DLAR 218.35,1997.36 r0 top
U7 "STLINK-V3MODS" STLINK-V3MODS 1174.57,3386.85 r0 top locked
VS1 "ESD5Z5.0T1G" SOD-523 464.95,3019.98 r180 top
X1 "ECS-300-10-37-CKM-TR" XTAL_SMD_2016 3274.61,1199.8 r0 top
X2 "ABS06-107-32.768KHZ-T" FP-ABS06-MFG 3204.72,1367.13 r90 top

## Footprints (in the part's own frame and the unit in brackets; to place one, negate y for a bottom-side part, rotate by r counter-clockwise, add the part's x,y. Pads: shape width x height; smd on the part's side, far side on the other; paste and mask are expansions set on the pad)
0201_DIODE [mm]
  rect 0.42x0.3 smd: A(0.31,0) K(-0.31,0)
  silkscreen extent -0.82,-0.33 -0.82,0.33
0201_res_rnd [mm]
  rrect50% 0.3x0.3 smd mask+0: 1(-0.25,0) 2(0.25,0)
0402_cap [mil]
  rect 22x20 smd: 1(-17,0) 2(17,0)
0402_cap_rnd [mil]
  rrect50% 22x20 smd: 1(-17,0) 2(17,0)
0402_res [mil]
  rect 22x20 smd: 1(-17,0) 2(17,0)
0603_cap [mm]
  rect 0.8x0.8 smd: 1(-0.8,0) 2(0.8,0)
0603_RES_AB_RA [mm]
  rrect50% 1x1 smd: A(-0.8,0) B(0.8,0) C(-0.8,1.6)
75915-308LF [mil] "CONN RCPT 8POS 0.1 GOLD PCB"
  rect 65x65 hole 35: 1(0,0)
  round 65 hole 35: 2(0,-100) 3(0,-200) 4(0,-300) 5(0,-400) 6(0,-500) 7(0,-600) 8(0,-700)
  silkscreen extent -50,-750 50,50
B2B-XH-A [mm] "JST 1x2 Header"
  rect 1.55x1.55 hole 1 paste+0 mask+0: 1(-1.25,0.525)
  round 1.55 hole 1 paste+0 mask+0: 2(1.25,0.525)
  silkscreen extent -3.7,-2.88 3.7,2.88
BLUENRGM2SP [mm]
  rect 1.2x1 smd: 1(-6.75,1.27) 2(-6.75,0) 3(-6.75,-1.27) 4(-6.75,-2.54) 5(-6.75,-3.81) 15(6.75,-3.81) 16(6.75,-2.54) 17(6.75,-1.27) 18(6.75,0) 19(6.75,1.27) 20(6.75,2.54)
  rect 1x1.2 smd: 6(-5.29,-4.81) 7(-4.02,-4.81) 8(-2.75,-4.81) 9(-1.48,-4.81) 10(-0.21,-4.81) 11(1.06,-4.81) 12(2.33,-4.81) 13(3.6,-4.81) 14(4.87,-4.81)
  silkscreen extent -8,1.17 6.75,6.69
CAPC0603X03N [mm] "Chip Capacitor, 2-Leads, Body 0.60x0.30mm, IPC Medium Density"
  rect 0.5x0.42 smd: 1(-0.31,0) 2(0.31,0)
CAPC1005X06N [mm] "Chip Capacitor, 2-Leads, Body 1.00x0.50mm, IPC Medium Density"
  rect 0.66x0.62 smd: 1(-0.44,0) 2(0.44,0)
CAPC1608X06L [mm] "Chip Capacitor, 2-Leads, Body 1.60x0.80mm, IPC High Density"
  rect 0.75x0.85 smd: 1(-0.65,0) 2(0.65,0)
CAPC1608X06N [mm] "Chip Capacitor, 2-Leads, Body 1.60x0.80mm, IPC Medium Density"
  rect 0.95x0.95 smd: 1(-0.75,0) 2(0.75,0)
CAPC3225X20N [mm] "Chip Capacitor, 2-Leads, Body 3.20x2.50mm, IPC Medium Density"
  rect 1.55x2.7 smd: 1(-1.325,0) 2(1.325,0)
  silkscreen extent -0.15,-1.25 0.15,1.25
DFN140P150X59-4N [mm] "DFN, 4-Leads, Body 1.50x1.50mm, Pitch 1.40mm, IPC Medium Density"
  rect 0.5x0.3 smd: 1(-0.7,0.4) 2(-0.7,-0.4) 3(0.7,-0.4) 4(0.7,0.4)
  silkscreen extent -1.35,-0.8 0.8,0.8
FIDUCIAL_1MM [mm]
  round 1 smd paste-1 mask+0: 1(0,0)
FP-5001-MFG [mm]
  round 1.57 hole 1.016 paste+0 mask+0: 1(0,0)
  silkscreen extent -1.35,-1.34 1.35,1.34
FP-ABS06-MFG [mm]
  rect 0.75x1.4 smd paste+0 mask+0: 1(-0.725,0) 2(0.725,0)
  silkscreen extent -1.07,-1.07 1.07,1.07
FP-QPC02SXGN-RC-MFG [mil]
FP-SOT23-IPC_A [mm]
  rect 1.874x0.612 smd paste+0 mask+0: 1(-0.935,0.95)
  rrect100% 1.874x0.612 smd paste+0 mask+0: 2(-0.935,-0.95) 3(0.935,0)
  silkscreen extent 0.38,-1.46 0.65,1.46
FTSH_108_D_K [mil]
  rect 40x40 hole 23.62: 1(-175,-25)
  round 40 hole 23.62: 2(-175,25) 3(-125,-25) 4(-125,25) 5(-75,-25) 6(-75,25) 7(-25,-25) 8(-25,25) 9(25,-25) 10(25,25) 11(75,-25) 12(75,25) 13(125,-25) 14(125,25) 15(175,-25) 16(175,25)
  silkscreen extent -210,-110 210,110
HDR1X2 [mm] "Connector; Header; 2 Position"
  rect 1.5x1.8 hole 0.9: 1(-1.27,0)
  oval 1.5x1.8 hole 0.9: 2(1.27,0)
  silkscreen extent -2.54,-1.27 2.54,1.27
HDR1X3 [mm] "Connector; Header; 3 Position"
  rect 1.5x1.5 hole 0.9: 1(-2.54,0)
  round 1.5 hole 0.9: 2(0,0) 3(2.54,0)
  silkscreen extent -3.81,-1.27 3.81,1.27
"HDR1X4 - Short Gold" [mm] "Connector; Header; 4 Position, 1x4"
  rect 1.5x1.5 hole 0.9: 1(-3.81,0)
  round 1.5 hole 0.9: 2(-1.27,0) 3(1.27,0) 4(3.81,0)
  silkscreen extent -5.08,-1.27 5.08,1.27
"HDR1X5 - Short Gold" [mm] "Connector; Header; 5 Position, 1x5"
  rect 1.5x1.5 hole 0.9: 1(-3.81,0)
  round 1.5 hole 0.9: 2(-1.27,0) 3(1.27,0) 4(3.81,0) 5(6.35,0)
  silkscreen extent -5.08,-1.3 7.68,1.3
"HDR2X8 Short Gold" [mm] "Connector; Header; 8x2 Position, 2x8"
  rect 1.5x1.8 hole 0.9: 1(-7.62,-1.27)
  oval 1.5x1.8 hole 0.9: 2(-7.62,1.27) 3(-5.08,-1.27) 4(-5.08,1.27) 5(-2.54,-1.27) 6(-2.54,1.27) 7(0,-1.27) 8(0,1.27) 9(2.54,-1.27) 10(2.54,1.27) 11(5.08,-1.27) 12(5.08,1.27) 13(7.62,-1.27) 14(7.62,1.27) 15(10.16,-1.27) 16(10.16,1.27)
  silkscreen extent -8.89,-2.54 11.43,2.54
"HDR2X9 Female" [mm] "Connector; Header; 9x2 Position, Female"
  rect 1.5x1.8 hole 0.9: 1(0,0)
  oval 1.5x1.8 hole 0.9: 2(0,2.54) 3(2.54,0) 4(2.54,2.54) 5(5.08,0) 6(5.08,2.54) 7(7.62,0) 8(7.62,2.54) 9(10.16,0) 10(10.16,2.54) 11(12.7,0) 12(12.7,2.54) 13(15.24,0) 14(15.24,2.54) 15(17.78,0) 16(17.78,2.54) 17(20.32,0) 18(20.32,2.54)
  silkscreen extent -1.27,-1.27 21.59,3.81
INDC1608X10N [mm] "Chip Inductor, 2-Leads, Body 1.60x0.80mm, IPC Medium Density"
  rect 0.93x1.02 smd: 1(-0.785,0) 2(0.785,0)
INDC2520X120N [mm]
  rect 1.24x2.22 smd: 1(-1.09,0) 2(1.09,0)
  silkscreen extent -0.15,-1.1 0.15,1.1
LED_0402_GREEN [mm]
  rect 0.7x0.5 smd: A(-0.45,0) K(0.45,0)
  silkscreen extent 0.92,-0.37 1.1,0.35
LED_0402_RED [mm]
  rect 0.7x0.5 smd: A(-0.45,0) K(0.45,0)
  silkscreen extent 0.93,-0.37 1.1,0.35
LED_0805_BLUE [mm]
  rect 1.2x1.2 smd: A(-1,0) K(1,0)
  silkscreen extent -1.83,-0.83 2.25,0.82
LED_0805_GREEN [mm]
  rect 1.2x1.2 smd: A(-1,0) K(1,0)
  silkscreen extent -1.83,-0.82 2.25,0.82
LED_0805_RED [mm]
  rect 1.2x1.2 smd: A(-1,0) K(1,0)
  silkscreen extent -1.83,-0.82 2.25,0.82
MF15 [mm]
  rect 0.6x0.6 smd: 1(0,0) 2(1,0) 3(2,0) 4(3,0) 5(4,0) 6(5,0) 7(6,0) 8(7,0) 9(8,0) 10(9,0) 11(10,0) 12(10,-1) 13(10,-2) 14(10,-3) 15(10,-4) 16(10,-5) 17(10,-6) 18(10,-7) 19(10,-8) 20(10,-9) 21(9,-9) 22(8,-9) 23(7,-9) 24(6,-9) 25(5,-9) 26(4,-9) 27(3,-9) 28(2,-9) 29(1,-9) 30(0,-9) 31(0,-8) 32(0,-7) 33(0,-6) 34(0,-5) 35(0,-4) 36(0,-3) 37(0,-2) 38(0,-1)
  silkscreen extent -0.6,-9.6 10.6,1.14
MH_300_275_NPTH [mm] "Non-plated mount hole M2.5 3.00mm diameter"
  round 2.75 hole 2.75 unplated mask+0: 1(0,0)
  Keep-Out Layer circle w0.2: c0,0 r1.65
MIKROBUS_Host_SD [mil] "MIKROBUS HOST SOCKET"
  silkscreen extent -100,-900 1000,225
QFN50P400X400X185_HS-25N [mm] "QFN, 24-Leads, Body 4.00x4.00mm, Pitch 0.50mm, Thermal Pad 2.35x2.35mm, IPC Medium Density"
  oval 0.85x0.35 smd paste-0.05 mask+0: 1(-1.9,1.25) 2(-1.9,0.75) 3(-1.9,0.25) 4(-1.9,-0.25) 5(-1.9,-0.75) 6(-1.9,-1.25) 13(1.9,-1.25) 14(1.9,-0.75) 15(1.9,-0.25) 16(1.9,0.25) 17(1.9,0.75)
  oval 0.35x0.85 smd paste-0.05 mask+0: 7(-1.25,-1.9) 8(-0.75,-1.9) 9(-0.25,-1.9) 10(0.25,-1.9) 11(0.75,-1.9) 12(1.25,-1.9) 19(1.25,1.9) 20(0.75,1.9) 21(0.25,1.9) 22(-0.25,1.9) 23(-0.75,1.9) 24(-1.25,1.9)
  oval 0.8x0.3 smd paste-0.05 mask+0: 18(1.9,1.25)
  rect 2.35x2.35 smd paste-0.05 mask+0: 25(0,0)
  silkscreen extent -2.92,-2.15 2.15,2.15
RESC1005X04N [mm] "Chip Resistor, 2-Leads, Body 1.00x0.50mm, IPC Medium Density"
  rect 0.66x0.62 smd: 1(-0.44,0) 2(0.44,0)
RESC1608X06N [mm] "Chip Resistor, 2-Leads, Body 1.55x0.80mm, IPC Medium Density"
  rect 0.95x0.95 smd: 1(-0.75,0) 2(0.75,0)
SCREW_TERM_2WAY_5MM [mm]
  round 2.2 hole 1.5: 1(0,0) 2(5,0)
  silkscreen extent -3.1,-3.8 8.13,4.2
SM04B-SRSS-TB [mm]
  rect 1.55x0.6 smd mask+0: 1(-1.937,1.5) 2(-1.937,0.5) 3(-1.937,-0.5) 4(-1.937,-1.5)
  rect 1.8x1.2 smd mask+0: 5(1.937,-2.8) 6(1.937,2.8)
  silkscreen extent -2.54,-3 2.41,3
SM2924-Footprint-1 [mm] "Footprint and 3D model for SM2924 component"
  rect 3.12x1 smd: 1(7.29,0)
  rect 2.54x2.47 smd: 2(7.001,-3.238) 2(7.001,3.239)
  Top Layer region: 7.255,2.404 7.255,2.2 8.718,2.2 8.718,2.404
  Top Layer region: 7.763,3.493 8.271,3.493 8.271,4.956 7.763,4.956
  Top Layer region: 8.718,2.912 8.718,3.42 7.255,3.42 7.255,2.912
  Top Layer region: 6.747,3.493 7.255,3.493 7.255,4.956 6.747,4.956
  Top Layer region: 8.718,3.928 8.718,4.436 7.255,4.436 7.255,3.928
  Top Layer region: 7.255,-3.928 7.255,-4.436 8.718,-4.436 8.718,-3.928
  Top Layer region: 6.747,-4.956 7.255,-4.956 7.255,-3.492 6.747,-3.492
  Top Layer region: 7.255,-2.912 7.255,-3.42 8.718,-3.42 8.718,-2.912
  Top Layer region: 7.763,-4.956 8.271,-4.956 8.271,-3.492 7.763,-3.492
  Top Layer region: 8.718,-2.404 8.718,-2.2 7.255,-2.2 7.255,-2.404
  Top Layer region: 5.791,5.235 5.791,4.727 7.254,4.727 7.254,5.235
  Top Layer region: 4.595,5.256 5.103,5.256 5.103,6.719 4.595,6.719
  Top Layer region: 5.611,5.256 6.119,5.256 6.119,6.719 5.611,6.719
  Top Layer region: 3.579,5.256 4.087,5.256 4.087,6.719 3.579,6.719
  Top Layer region: 2.563,5.256 3.071,5.256 3.071,6.719 2.563,6.719
  Top Layer region: 1.547,5.256 2.055,5.256 2.055,6.719 1.547,6.719
  Top Layer region: 0.531,5.256 1.039,5.256 1.039,6.719 0.531,6.719
  Top Layer region: -0.485,5.256 0.023,5.256 0.023,6.719 -0.485,6.719
  Top Layer region: -0.485,-6.719 0.023,-6.719 0.023,-5.256 -0.485,-5.256
  Top Layer region: 0.531,-6.719 1.039,-6.719 1.039,-5.256 0.531,-5.256
  Top Layer region: 1.547,-6.719 2.055,-6.719 2.055,-5.256 1.547,-5.256
  Top Layer region: 2.563,-6.719 3.071,-6.719 3.071,-5.256 2.563,-5.256
  Top Layer region: 3.579,-6.719 4.087,-6.719 4.087,-5.256 3.579,-5.256
  Top Layer region: 5.611,-6.719 6.119,-6.719 6.119,-5.256 5.611,-5.256
  Top Layer region: 4.595,-6.719 5.103,-6.719 5.103,-5.256 4.595,-5.256
  Top Layer region: 7.254,-5.235 7.254,-4.727 5.791,-4.727 5.791,-5.235
  Top Layer keep-out lines w0: 8.977,2 5.73,2 5.73,0.627 8.977,0.627 8.977,2 ; 8.977,-0.627 8.977,-2 5.73,-2 5.73,-0.627 8.977,-0.627
  Keep-Out Layer lines w0.013: -1.131,3.565 4.35,3.565 cw(c4.85,3.565) 5.35,3.565 5.35,-3.565 cw(c4.85,-3.565) 4.35,-3.565 -1.131,-3.565
SOD-123FL [mm] "Surface Mount Schottky Diode"
  rect 0.91x1.22 smd: A(1.64,0) K(-1.64,0)
  silkscreen extent -1.35,-0.82 1.35,0.82
SOD-523 [mm]
  rect 0.5x0.4 smd: A(0.65,0) K(-0.65,0)
  silkscreen extent -1.2,-0.38 0.4,0.4
SOD-523-DIODE [mm]
  rect 0.5x0.4 smd: A(0.65,0) K(-0.65,0)
  silkscreen extent -0.4,-0.38 0.4,0.4
SOT95P240X120_GSD-3N(SOT23-3L) [mm] "SOT23, 3-Leads, Body 2.90x2.35mm, Pitch 0.95mm, IPC High Density"
  rrect50% 1x1.4 smd: D(0,1.019) G(-0.95,-1.1) S(0.95,-1.1)
  silkscreen extent -1.56,-0.2 1.56,0.75
STLINK-V3MODS [mil]
  rect 74.8x42.13 smd paste+0 mask+0: 1(-288.19,-390) 2(-288.19,-440) 3(-288.19,-490) 4(-288.19,-540) 5(-288.19,-590) 6(-288.19,-640) 7(-288.19,-690) 8(-288.19,-740) 9(-288.19,-790) 10(-288.19,-840) 11(-288.19,-890) 12(-288.19,-940) 13(-288.19,-990) 14(-288.19,-1040) 15(-288.19,-1090) 16(-288.19,-1140) 17(288.19,-1140) 18(288.19,-1090) 19(288.19,-1040) 20(288.19,-990) 21(288.19,-940) 22(288.19,-890) 23(288.19,-840) 24(288.19,-790) 25(288.19,-740) 26(288.19,-690) 27(288.19,-640) 28(288.19,-590) 29(288.19,-540) 30(288.19,-490) 31(288.19,-440) 32(288.19,-390)
  silkscreen extent -300,-1180 300,0
STM32U585VIT6 [mm]
  rect 1.475x0.3 smd: 1(-7.738,6) 2(-7.738,5.5) 3(-7.738,5) 4(-7.738,4.5) 5(-7.738,4) 6(-7.738,3.5) 7(-7.738,3) 8(-7.738,2.5) 9(-7.738,2) 10(-7.738,1.5) 11(-7.738,1) 12(-7.738,0.5) 13(-7.738,0) 14(-7.738,-0.5) 15(-7.738,-1) 16(-7.738,-1.5) 17(-7.738,-2) 18(-7.738,-2.5) 19(-7.738,-3) 20(-7.738,-3.5) 21(-7.738,-4) 22(-7.738,-4.5) 23(-7.738,-5) 24(-7.738,-5.5) 25(-7.738,-6) 51(7.738,-6) 52(7.738,-5.5) 53(7.738,-5) 54(7.738,-4.5) 55(7.738,-4) 56(7.738,-3.5) 57(7.738,-3) 58(7.738,-2.5) 59(7.738,-2) 60(7.738,-1.5) 61(7.738,-1) 62(7.738,-0.5) 63(7.738,0) 64(7.738,0.5) 65(7.738,1) 66(7.738,1.5) 67(7.738,2) 68(7.738,2.5) 69(7.738,3) 70(7.738,3.5) 71(7.738,4) 72(7.738,4.5) 73(7.738,5) 74(7.738,5.5) 75(7.738,6)
  rect 0.3x1.475 smd: 26(-6,-7.738) 27(-5.5,-7.738) 28(-5,-7.738) 29(-4.5,-7.738) 30(-4,-7.738) 31(-3.5,-7.738) 32(-3,-7.738) 33(-2.5,-7.738) 34(-2,-7.738) 35(-1.5,-7.738) 36(-1,-7.738) 37(-0.5,-7.738) 38(0,-7.738) 39(0.5,-7.738) 40(1,-7.738) 41(1.5,-7.738) 42(2,-7.738) 43(2.5,-7.738) 44(3,-7.738) 45(3.5,-7.738) 46(4,-7.738) 47(4.5,-7.738) 48(5,-7.738) 49(5.5,-7.738) 50(6,-7.738) 76(6,7.738) 77(5.5,7.738) 78(5,7.738) 79(4.5,7.738) 80(4,7.738) 81(3.5,7.738) 82(3,7.738) 83(2.5,7.738) 84(2,7.738) 85(1.5,7.738) 86(1,7.738) 87(0.5,7.738) 88(0,7.738) 89(-0.5,7.738) 90(-1,7.738) 91(-1.5,7.738) 92(-2,7.738) 93(-2.5,7.738) 94(-3,7.738) 95(-3.5,7.738) 96(-4,7.738) 97(-4.5,7.738) 98(-5,7.738) 99(-5.5,7.738) 100(-6,7.738)
  silkscreen extent -8.35,-6.65 6.65,6.87
TL1105 [mm]
  round 1.6 hole 1: 1(0,0) 2(6.5,0) 3(6.5,4.5) 4(0,4.5)
  silkscreen extent 0.25,-0.75 6.25,5.25
TPS63802DLAR [mm]
  rect 0.6x0.25 smd paste+0 mask+0: 1(-0.9,1) 2(-0.9,0.5) 3(-0.9,0) 4(-0.9,-0.5) 5(-0.9,-1)
  rect 0.9x0.25 smd paste+0 mask+0: 6(0.75,-1) 7(0.75,-0.5) 9(0.75,0.5) 10(0.75,1)
  rect 1.3x0.25 smd paste-0.637 mask+0: 8(0.55,0)
  silkscreen extent -1,-1.65 1,1.65
U_FL-R-SMT [mm]
  rrect50% 1x1 smd: 1(0,-1.5)
  rect 1.05x2.2 smd: 2(-1.475,0) 3(1.475,0)
  Top Layer keep-out region: -1.499,-1.55 1.501,-1.55 1.501,1.55 -1.499,1.55
  silkscreen extent -1.55,-1.52 1.55,1.5
USB-C_RCP [mm] "CONN RCP USB3.1 TYPEC 24P SMD RA"
  rect 0.28x0.7 smd mask+0: A1(-3,3.085) A2(-2.5,3.085) A3(-2,3.085) A4(-1.5,3.085) A5(-1,3.085) A6(-0.5,3.085) A7(0.5,3.085) A8(1,3.085) A9(1.5,3.085) A10(2,3.085) A11(2.5,3.085) A12(3,3.085) B2(2.25,1.385) B3(1.75,1.385) B4(1.25,1.385) B5(0.75,1.385) B6(0.25,1.385) B7(-0.25,1.385) B8(-0.75,1.385) B9(-1.25,1.385) B10(-1.75,1.385) B11(-2.25,1.385)
  rect 0.88x0.7 smd mask+0: B1(3.05,1.385) B12(-3.05,1.385)
  oval 1.1x2.1 hole 0.6 slot 1.6 at 90 deg: SH1(-4.32,2.275) SH2(4.32,2.275)
  oval 1.1x3.6 hole 0.6 slot 2.1 at 90 deg copper offset 0,0.5: SH3(4.62,-3.085) SH4(-4.62,-3.085)
  silkscreen extent -3.76,3.65 -3.51,3.9
USON8P20X30X6 [mm] "8-Pad USON 2x3x0.6mm"
  rect 0.8x0.25 smd: 1(-1.345,0.75) 2(-1.345,0.25) 3(-1.345,-0.25) 4(-1.345,-0.75) 5(1.345,-0.75) 6(1.345,-0.25) 7(1.345,0.25) 8(1.345,0.75)
  rect 0.2x1.6 smd: 9(0,0)
  silkscreen extent -1.9,1.19 -1.8,1.29
WL-SFCW_1206 [mm] "SMT Full-color Chip LED Waterclear, body 3.2x1.6mm"
  rect 1.6x1.2 smd: 1(-1.5,0.8) 2(-1.5,-0.8) 3(1.5,-0.8) 4(1.5,0.8)
  silkscreen extent -2.92,-0.79 0.41,0.81
XTAL_SMD_2016 [mm] "XTAL 4-pin SMD 2016"
  rect 0.85x0.75 smd mask+0: 1(-0.675,-0.525) 2(0.675,-0.525) 3(0.675,0.525) 4(-0.675,0.525)
  silkscreen extent -1.5,-1.1 -1.3,-0.9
